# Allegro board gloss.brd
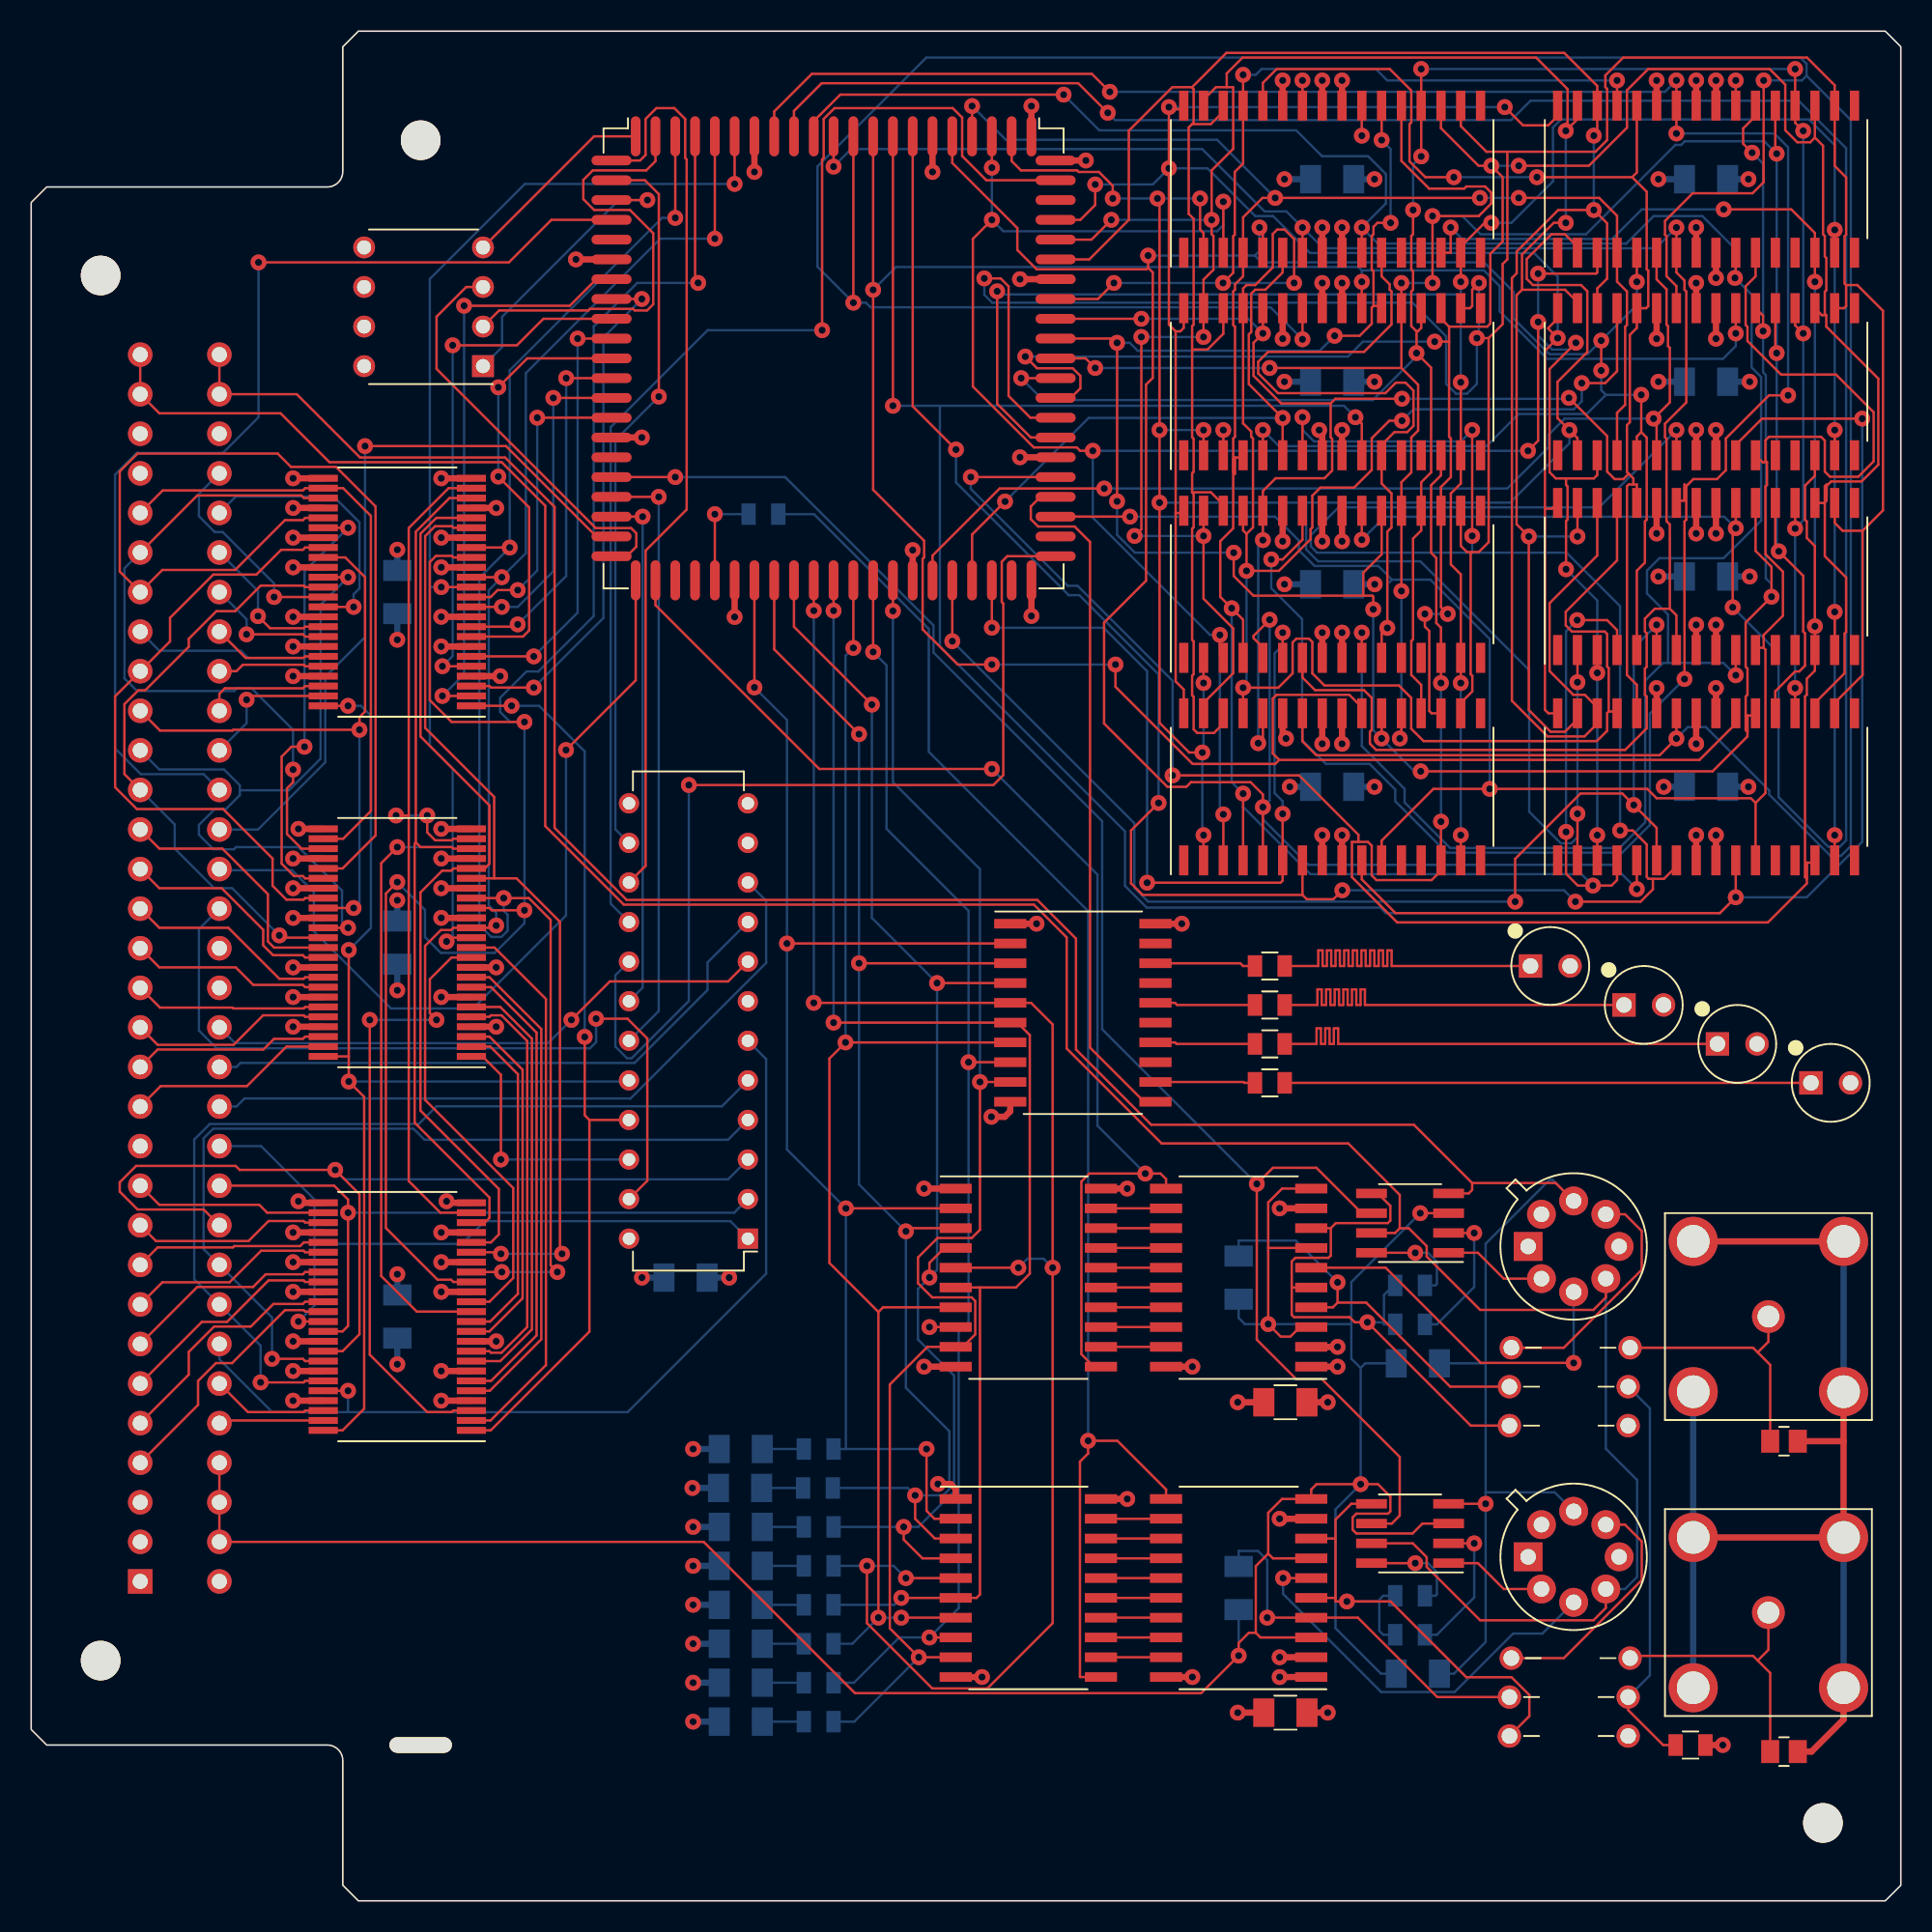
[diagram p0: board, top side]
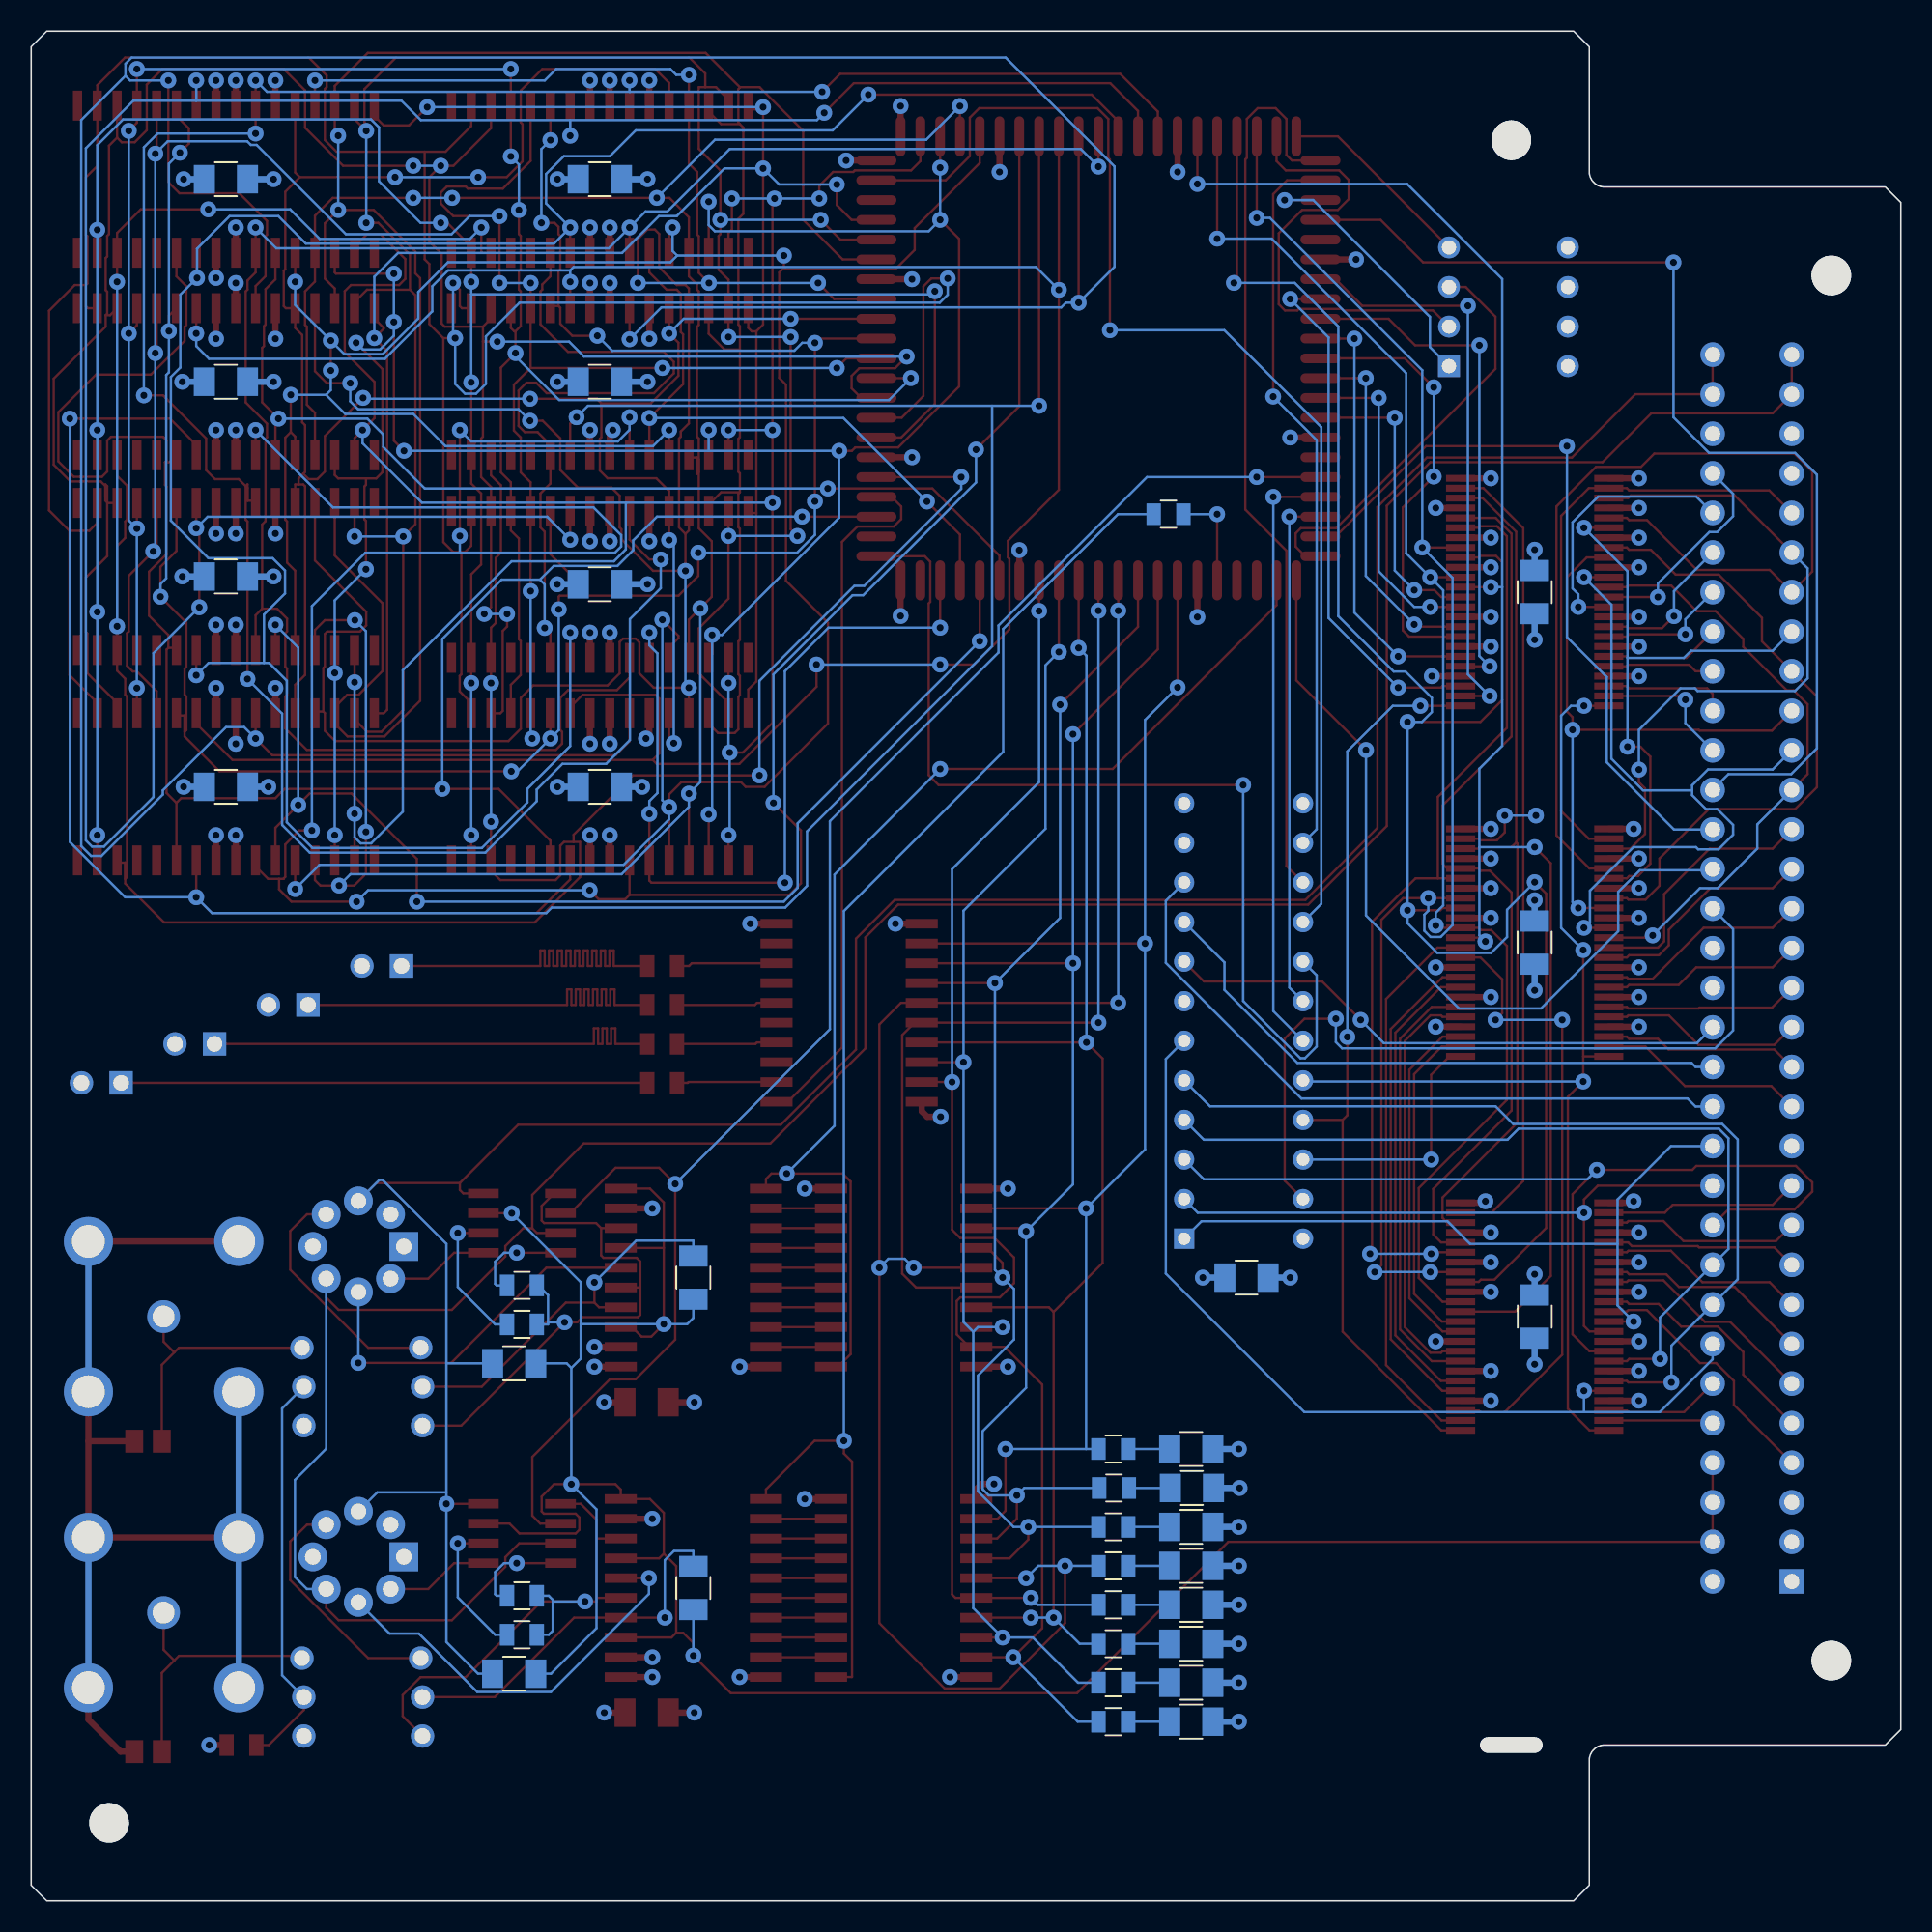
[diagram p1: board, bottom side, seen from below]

Outline 120 x 120 mm; copper layers: TOP, GND1, VCC1, VCC2, GND2, BOTTOM. Coordinates in mm from the lower left corner of the outline.

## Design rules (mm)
constraint set DEFAULT: min track width 0.15
net group LEDNETS: nets LED1 LED2 LED3 LED4
net group MEMORY[0..28]: nets MEMORY.RA0 MEMORY.RA1 MEMORY.RA2 MEMORY.RA3 MEMORY.RA4 MEMORY.RA5 MEMORY.RA6 MEMORY.RA7 MEMORY.RA8 MEMORY.RA9 MEMORY.RA10 MEMORY.RA11 MEMORY.RA12 MEMORY.RA13 MEMORY.RA14 MEMORY.RA15 MEMORY.RCS0 MEMORY.RCS1 MEMORY.RCS2 MEMORY.RCS3 MEMORY.RD0 MEMORY.RD1 MEMORY.RD2 MEMORY.RD3 MEMORY.RD4 MEMORY.RD5 MEMORY.RD6 MEMORY.RD7 MEMORY.RWE
net group POWER: nets GND_EARTH
nets with their own width: min track width 0.4; nets GND VCC

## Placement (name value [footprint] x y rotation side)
C1  0.1uF  [CAPC3216X110N]  23.5 37.5 90 bottom
C2  0.1uF  [CAPC3216X110N]  42 40 0 bottom
C3  0.1uF  [CAPC3216X110N]  23.5 61.5 90 bottom
C4  0.1uF  [CAPC3216X110N]  23.5 84 90 bottom
C5  47PF  [CAPC2012X110N]  112.5 29.5 0 top
C6  47PF  [CAPC2012X110N]  112.5 9.58 0 top
C7  0.01u  [CAPC3216X110N]  80.5 32 180 top
C8  0.01u  [CAPC3216X110N]  77.5 40 270 bottom
C9  0.1u  [CAPC3216X110N]  89 34.5 180 bottom
C10  0.01u  [CAPC3216X110N]  80.5 12.08 180 top
C11  0.01u  [CAPC3216X110N]  77.5 20.08 270 bottom
C12  0.1u  [CAPC3216X110N]  89 14.58 180 bottom
C13  330p  [CAPC3216X110N]  45.55 14 180 bottom
C14  330p  [CAPC3216X110N]  45.55 19 180 bottom
C15  330p  [CAPC3216X110N]  45.55 24 180 bottom
C16  330p  [CAPC3216X110N]  45.55 29 180 bottom
C17  330p  [CAPC3216X110N]  45.55 11.5 180 bottom
C18  330p  [CAPC3216X110N]  45.55 16.5 180 bottom
C19  330p  [CAPC3216X110N]  45.55 21.5 180 bottom
C20  330p  [CAPC3216X110N]  45.5 26.5 180 bottom
C21  0.1uF  [CAPC3216X110N]  107.5 85 0 bottom
C22  0.1uF  [CAPC3216X110N]  107.5 97.5 0 bottom
C23  0.1uF  [CAPC3216X110N]  107.5 110.5 0 bottom
C24  0.1uF  [CAPC3216X110N]  107.5 71.5 0 bottom
C25  0.1uF  [CAPC3216X110N]  83.5 71.5 0 bottom
C26  0.1uF  [CAPC3216X110N]  83.5 84.5 0 bottom
C27  0.1uF  [CAPC3216X110N]  83.5 110.5 0 bottom
C28  0.1uF  [CAPC3216X110N]  83.5 97.5 0 bottom
D1  LED  [LEDRD254W00D500H860P]  97.5 60 0 top
D2  LED  [LEDRD254W00D500H860P]  103.5 57.5 0 top
D3  LED  [LEDRD254W00D500H860P]  109.5 55 0 top
D4  LED  [LEDRD254W00D500H860P]  115.5 52.5 0 top
J1  CON64  [DIN64]  7 20.5 0 top
J2  BNC  [CONNEX_112659]  111.5 37.5 0 top
J3  BNC  [CONNEX_112659]  111.5 18.5 0 top
L1  47u  [INDAD762W79L381D254P]  95 35.5 0 top
L2  47u  [INDAD762W79L381D254P]  95 15.58 0 top
L3  47u  [INDAD762W79L381D254P]  102.5 33 180 top
L4  47u  [INDAD762W79L381D254P]  102.5 30.5 180 top
L5  47u  [INDAD762W79L381D254P]  102.5 13.08 180 top
L6  47u  [INDAD762W79L381D254P]  102.5 10.58 180 top
NOREF  -  []  26.7 0 90 top
NOREF#2  -  []  25 10 0 top
NOREF#3  -  []  119.51 119.49 0 top
NOREF#4  -  []  0 23.55 0 top
NOREF#5  -  [unnamed#2]  25 10 0 top
NOREF#6  -  []  25 10 90 top
NOREF#7  -  []  115 5 90 top
NOREF#8  -  []  20 6.63 0 top
NOREF#9  -  []  195.18 157.32 0 top
NOREF#10  -  []  25 10 90 top
NOREF#11  -  []  -74.06 -89.06 0 top
NOREF#12  -  []  19.74 110.33 0 top
NOREF#13  -  []  25 10 0 top
NOREF#14  -  []  25 10 90 top
R1  150  [RESC2012X60N]  79.5 60 0 top
R2  150  [RESC2012X60N]  79.5 57.5 0 top
R3  150  [RESC2012X60N]  79.5 55 0 top
R4  150  [RESC2012X60N]  79.5 52.5 0 top
R5  2K  [RESC2012X60N]  47 89 0 bottom
R6  100  [RESC2012X60N]  88.5 39.5 0 bottom
R7  100  [RESC2012X60N]  88.5 37 0 bottom
R8  100  [RESC2012X60N]  88.5 19.58 0 bottom
R9  100  [RESC2012X60N]  88.5 17.08 0 bottom
R10  10K  [RESC2012X60N]  50.55 14 0 bottom
R11  10K  [RESC2012X60N]  50.55 19 0 bottom
R12  10K  [RESC2012X60N]  50.55 24 0 bottom
R13  10K  [RESC2012X60N]  50.55 29 0 bottom
R14  10K  [RESC2012X60N]  50.55 11.5 0 bottom
R15  10K  [RESC2012X60N]  50.55 16.5 0 bottom
R16  10K  [RESC2012X60N]  50.55 21.5 0 bottom
R17  10K  [RESC2012X60N]  50.5 26.5 0 bottom
R18  10K  [RESC2012X60N]  106.5 10 0 top
U1  FCT16245  [SOP63P1035X279-48N]  23.5 37.5 90 top
U2  20L10  [DIP763W46P254L3204H508Q24P]  46 42.5 90 top
U3  FCT16245  [SOP63P1035X279-48N]  23.5 61.5 90 top
U4  FCT16245  [SOP63P1035X279-48N]  23.5 84 90 top
U5  EPF8282A_LCC  [PLCC127P3022X3022X457-84N]  51.5 99 270 top
U6  74ACT574  [SOIC127P1034X264-20N]  67.5 57 270 top
U7  EPC1064  [DIP763W46P254L991H419Q8P]  29 98.5 90 top
U8  TLC5602A  [SOIC127P1034X264-20N]  77.5 40 90 top
U9  TLE2037A  [TO292P469H584-8P]  99 42 0 top
U10  DG419AK  [SOIC127P600X175-8N]  88.5 43.5 90 top
U11  TLC5602A  [SOIC127P1034X264-20N]  77.5 20.08 90 top
U12  TLE2037A  [TO292P469H584-8P]  99 22.08 0 top
U13  DG419AK  [SOIC127P600X175-8N]  88.5 23.58 90 top
U14  74ACT574  [SOIC127P1034X264-20N]  64 40 270 top
U15  74ACT574  [SOIC127P1034X264-20N]  64 20.08 270 top
U16  TC55B4257  [SOIC127P1032X265-32N]  83.5 71.5 0 top
U17  TC55B4257  [SOIC127P1032X265-32N]  83.5 84.5 0 top
U18  TC55B4257  [SOIC127P1032X265-32N]  83.5 97.5 0 top
U19  TC55B4257  [SOIC127P1032X265-32N]  83.5 110.5 0 top
U20  TC55B4257  [SOIC127P1032X265-32N]  107.5 71.5 0 top
U21  TC55B4257  [SOIC127P1032X265-32N]  107.5 85 0 top
U22  TC55B4257  [SOIC127P1032X265-32N]  107.5 97.5 0 top
U23  TC55B4257  [SOIC127P1032X265-32N]  107.5 110.5 0 top

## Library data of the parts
C1-C4 C13-C20 = CAP NP
C5 C7-C9 = CAP NP: room: CHAN1
C6 C10-C12 = CAP NP: room: CHAN2
C21-C28 = CAP NP: room: MEM
D1-D4 = PHOTODIODE_0
J1 = CON64
J2 = BNC: room: CHAN1
J3 = BNC: room: CHAN2
L1 L3 L4 = INDUCTOR: room: CHAN1
L2 L5 L6 = INDUCTOR: room: CHAN2
R1-R4 = R: room: LED
R5 R10-R17 = R
R6 R7 = R: room: CHAN1
R8 R9 R18 = R: room: CHAN2
U1 U3 U4 = FCT16245
U2 = 20L10: alternate symbols: (T:SOIC24;B:SOIC24_PE)
U5 = EPF8282A/LCC
U6 = 74ACT574: room: LED
U7 = EPC1064
U8 = TLC5602A: room: CHAN1
U9 = TLE2037A: room: CHAN1
U10 = DG419AK: room: CHAN1
U11 = TLC5602A: room: CHAN2
U12 = TLE2037A: room: CHAN2
U13 = DG419AK: room: CHAN2
U14 = 74ACT574: room: CHAN1
U15 = 74ACT574: room: CHAN2
U16-U23 = TC55B4257: room: MEM

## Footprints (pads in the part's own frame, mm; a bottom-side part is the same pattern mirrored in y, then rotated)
CAPC2012X110N
  rect 1.15x1.47 smd: 1(-0.885,0) 2(0.885,0)
CAPC3216X110N
  rect 1.35x1.82 smd: 1(-1.385,0) 2(1.385,0)
CONNEX_112659
  round 2.1 hole 1.4: 1(0,0)
  round 3.15 hole 2.1: 2(-4.825,4.825) 3(4.825,4.825) 4(4.825,-4.825) 5(-4.825,-4.825)
DIN64
  round 2.54 hole 2.794 unplated: (-2.54,83.82) (-2.54,-5.08)
  rect 1.575x1.575 hole 0.965: 1(0,0)
  round 1.575 hole 0.965: 2(0,2.54) 3(0,5.08) 4(0,7.62) 5(0,10.16) 6(0,12.7) 7(0,15.24) 8(0,17.78) 9(0,20.32) 10(0,22.86) 11(0,25.4) 12(0,27.94) 13(0,30.48) 14(0,33.02) 15(0,35.56) 16(0,38.1) 17(0,40.64) 18(0,43.18) 19(0,45.72) 20(0,48.26) 21(0,50.8) 22(0,53.34) 23(0,55.88) 24(0,58.42) 25(0,60.96) 26(0,63.5) 27(0,66.04) 28(0,68.58) 29(0,71.12) 30(0,73.66) 31(0,76.2) 32(0,78.74) 33(5.08,0) 34(5.08,2.54) 35(5.08,5.08) 36(5.08,7.62) 37(5.08,10.16) 38(5.08,12.7) 39(5.08,15.24) 40(5.08,17.78) 41(5.08,20.32) 42(5.08,22.86) 43(5.08,25.4) 44(5.08,27.94) 45(5.08,30.48) 46(5.08,33.02) 47(5.08,35.56) 48(5.08,38.1) 49(5.08,40.64) 50(5.08,43.18) 51(5.08,45.72) 52(5.08,48.26) 53(5.08,50.8) 54(5.08,53.34) 55(5.08,55.88) 56(5.08,58.42) 57(5.08,60.96) 58(5.08,63.5) 59(5.08,66.04) 60(5.08,68.58) 61(5.08,71.12) 62(5.08,73.66) 63(5.08,76.2) 64(5.08,78.74)
DIP763W46P254L991H419Q8P
  rect 1.4x1.4 hole 0.9: 1(0,0)
  round 1.4 hole 0.9: 2(2.54,0) 3(5.08,0) 4(7.62,0) 5(7.62,7.63) 6(5.08,7.63) 7(2.54,7.63) 8(0,7.63)
DIP763W46P254L3204H508Q24P
  rect 1.3x1.3 hole 0.8: 1(0,0)
  round 1.3 hole 0.8: 2(2.54,0) 3(5.08,0) 4(7.62,0) 5(10.16,0) 6(12.7,0) 7(15.24,0) 8(17.78,0) 9(20.32,0) 10(22.86,0) 11(25.4,0) 12(27.94,0) 13(27.94,7.63) 14(25.4,7.63) 15(22.86,7.63) 16(20.32,7.63) 17(17.78,7.63) 18(15.24,7.63) 19(12.7,7.63) 20(10.16,7.63) 21(7.62,7.63) 22(5.08,7.63) 23(2.54,7.63) 24(0,7.63)
INDAD762W79L381D254P
  round 1.5 hole 1: 1(0,0) 2(7.62,0)
LEDRD254W00D500H860P
  round 1.5 hole 1: A(1.27,0)
  rect 1.5x1.5 hole 1: C(-1.27,0)
PLCC127P3022X3022X457-84N
  oval 2.57x0.62 smd: 1(-14.25,0) 2(-14.25,-1.27) 3(-14.25,-2.54) 4(-14.25,-3.81) 5(-14.25,-5.08) 6(-14.25,-6.35) 7(-14.25,-7.62) 8(-14.25,-8.89) 9(-14.25,-10.16) 10(-14.25,-11.43) 11(-14.25,-12.7) 33(14.25,-12.7) 34(14.25,-11.43) 35(14.25,-10.16) 36(14.25,-8.89) 37(14.25,-7.62) 38(14.25,-6.35) 39(14.25,-5.08) 40(14.25,-3.81) 41(14.25,-2.54) 42(14.25,-1.27) 43(14.25,0) 44(14.25,1.27) 45(14.25,2.54) 46(14.25,3.81) 47(14.25,5.08) 48(14.25,6.35) 49(14.25,7.62) 50(14.25,8.89) 51(14.25,10.16) 52(14.25,11.43) 53(14.25,12.7) 75(-14.25,12.7) 76(-14.25,11.43) 77(-14.25,10.16) 78(-14.25,8.89) 79(-14.25,7.62) 80(-14.25,6.35) 81(-14.25,5.08) 82(-14.25,3.81) 83(-14.25,2.54) 84(-14.25,1.27)
  oval 0.62x2.57 smd: 12(-12.7,-14.25) 13(-11.43,-14.25) 14(-10.16,-14.25) 15(-8.89,-14.25) 16(-7.62,-14.25) 17(-6.35,-14.25) 18(-5.08,-14.25) 19(-3.81,-14.25) 20(-2.54,-14.25) 21(-1.27,-14.25) 22(0,-14.25) 23(1.27,-14.25) 24(2.54,-14.25) 25(3.81,-14.25) 26(5.08,-14.25) 27(6.35,-14.25) 28(7.62,-14.25) 29(8.89,-14.25) 30(10.16,-14.25) 31(11.43,-14.25) 32(12.7,-14.25) 54(12.7,14.25) 55(11.43,14.25) 56(10.16,14.25) 57(8.89,14.25) 58(7.62,14.25) 59(6.35,14.25) 60(5.08,14.25) 61(3.81,14.25) 62(2.54,14.25) 63(1.27,14.25) 64(0,14.25) 65(-1.27,14.25) 66(-2.54,14.25) 67(-3.81,14.25) 68(-5.08,14.25) 69(-6.35,14.25) 70(-7.62,14.25) 71(-8.89,14.25) 72(-10.16,14.25) 73(-11.43,14.25) 74(-12.7,14.25)
RESC2012X60N
  rect 0.92x1.38 smd: 1(-0.955,0) 2(0.955,0)
SOIC127P600X175-8N
  rect 0.6x1.97 smd: 1(-1.905,-2.475) 2(-0.635,-2.475) 3(0.635,-2.475) 4(1.905,-2.475) 5(1.905,2.475) 6(0.635,2.475) 7(-0.635,2.475) 8(-1.905,2.475)
SOIC127P1032X265-32N
  rect 0.59x1.92 smd: 1(-9.525,-4.72) 2(-8.255,-4.72) 3(-6.985,-4.72) 4(-5.715,-4.72) 5(-4.445,-4.72) 6(-3.175,-4.72) 7(-1.905,-4.72) 8(-0.635,-4.72) 9(0.635,-4.72) 10(1.905,-4.72) 11(3.175,-4.72) 12(4.445,-4.72) 13(5.715,-4.72) 14(6.985,-4.72) 15(8.255,-4.72) 16(9.525,-4.72) 17(9.525,4.72) 18(8.255,4.72) 19(6.985,4.72) 20(5.715,4.72) 21(4.445,4.72) 22(3.175,4.72) 23(1.905,4.72) 24(0.635,4.72) 25(-0.635,4.72) 26(-1.905,4.72) 27(-3.175,4.72) 28(-4.445,4.72) 29(-5.715,4.72) 30(-6.985,4.72) 31(-8.255,4.72) 32(-9.525,4.72)
SOIC127P1034X264-20N
  rect 0.61x2.06 smd: 1(-5.715,-4.66) 2(-4.445,-4.66) 3(-3.175,-4.66) 4(-1.905,-4.66) 5(-0.635,-4.66) 6(0.635,-4.66) 7(1.905,-4.66) 8(3.175,-4.66) 9(4.445,-4.66) 10(5.715,-4.66) 11(5.715,4.66) 12(4.445,4.66) 13(3.175,4.66) 14(1.905,4.66) 15(0.635,4.66) 16(-0.635,4.66) 17(-1.905,4.66) 18(-3.175,4.66) 19(-4.445,4.66) 20(-5.715,4.66)
SOP63P1035X279-48N
  rect 0.44x1.87 smd: 1(-7.302,-4.755) 2(-6.668,-4.755) 3(-6.032,-4.755) 4(-5.398,-4.755) 5(-4.762,-4.755) 6(-4.128,-4.755) 7(-3.492,-4.755) 8(-2.858,-4.755) 9(-2.222,-4.755) 10(-1.588,-4.755) 11(-0.952,-4.755) 12(-0.318,-4.755) 13(0.318,-4.755) 14(0.952,-4.755) 15(1.588,-4.755) 16(2.222,-4.755) 17(2.858,-4.755) 18(3.492,-4.755) 19(4.128,-4.755) 20(4.762,-4.755) 21(5.398,-4.755) 22(6.032,-4.755) 23(6.668,-4.755) 24(7.302,-4.755) 25(7.302,4.755) 26(6.668,4.755) 27(6.032,4.755) 28(5.398,4.755) 29(4.762,4.755) 30(4.128,4.755) 31(3.492,4.755) 32(2.858,4.755) 33(2.222,4.755) 34(1.588,4.755) 35(0.952,4.755) 36(0.318,4.755) 37(-0.318,4.755) 38(-0.952,4.755) 39(-1.588,4.755) 40(-2.222,4.755) 41(-2.858,4.755) 42(-3.492,4.755) 43(-4.128,4.755) 44(-4.762,4.755) 45(-5.398,4.755) 46(-6.032,4.755) 47(-6.668,4.755) 48(-7.302,4.755)
TO292P469H584-8P
  rect 1.85x1.85 hole 1: 1(-2.921,0)
  round 1.85 hole 1: 2(-2.066,-2.066) 3(0,-2.921) 4(2.066,-2.066) 5(2.921,0) 6(2.066,2.066) 7(0,2.921) 8(-2.066,2.066)
unnamed#2
  round 2.54 hole 2.794 unplated: (0,103) (90,-5)
  oval 4x1 hole 5x1.5 unplated: (0,0)

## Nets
AGND: C8.2 C9.2 C11.2 C12.2 J1.34 J1.35 J1.36 U8.3 U8.7 U8.10 U10.3 U11.3 U11.7 U11.10 U13.3
GND: C1.2 C2.2 C3.2 C4.2 C7.2 C10.2 C13.2 C14.2 C15.2 C16.2 C17.2 C18.2 C19.2 C20.2 C21.2 C22.2 C23.2 C24.2 C25.2 C26.2 C27.2 C28.2 J1.1 J1.2 J1.3 J1.33 R18.2 U1.4 U1.10 U1.15 U1.21 U1.24 U1.25(G\) U1.28 U1.34 U1.39 U1.45 U2.11 U2.12 U2.13 U3.4 U3.10 U3.15 U3.21 U3.24 U3.25(G\) U3.28 U3.34 U3.39 U3.45 U4.4 U4.10 U4.15 U4.21 U4.24 U4.25(G\) U4.28 U4.34 U4.39 U4.45 U5.5 U5.26 U5.47 U5.53 U5.68 U5.74 U5.75 U6.1 U6.10 U7.5 U8.1 U8.20 U11.1 U11.20 U14.1 U14.10 U15.1 U15.10 U16.9 U16.25 U16.27 U17.9 U17.25 U17.27 U18.9 U18.25 U18.27 U19.9 U19.25 U19.27 U20.9 U20.25 U20.27 U21.9 U21.25 U21.27 U22.9 U22.25 U22.27 U23.9 U23.25 U23.27
GND_EARTH: C5.2 C6.2 J2.2 J2.3 J2.4 J2.5(GND5) J3.2 J3.3 J3.4 J3.5(GND5)
V12N: J1.31 J1.32 U9.4(V-) U10.7 U12.4(V-) U13.7
VCC: C1.1 C2.1 C3.1 C4.1 C7.1 C10.1 C21.1 C22.1 C23.1 C24.1 C25.1 C26.1 C27.1 C28.1 D1.A D2.A D3.A D4.A J1.29 J1.30 J1.62 L4.1 L6.1 U1.7 U1.18 U1.31 U1.42 U2.24(VCC) U3.7 U3.18 U3.31 U3.42 U4.7 U4.18 U4.31 U4.42 U5.17 U5.38 U5.59 U5.80 U6.20 U7.7 U7.8 U8.2 U8.9(VD2) U11.2 U11.9(VD2) U14.20 U15.20 U16.8 U16.24 U17.8 U17.24 U18.8 U18.24 U19.8 U19.24 U20.8 U20.24 U21.8 U21.24 U22.8 U22.24 U23.8 U23.24
A0: J1.54 U4.47
A1: J1.55 U4.46
A2: J1.56 U4.44
A3: J1.57 U4.43
A4: J1.58 U4.41
A5: J1.59 U4.40
A6: J1.60 U4.38
A7: J1.61 U4.37
A8: J1.13 U3.47
A9: J1.14 U3.46
A10: J1.15 U3.44
A11: J1.16 U3.43
A12: J1.17 U3.41
A13: J1.18 U3.40
A14: J1.19 U3.38
A15: J1.20 U3.37
A16: J1.37 U1.47
A17: J1.38 U1.46
A18: J1.39 U1.44 U2.6
A19: J1.40 U1.43 U2.5
A20: J1.41 U1.41 U2.4
A21: J1.42 U1.40 U2.3
A22: J1.43 U1.38 U2.2
A23: J1.44 U1.37 U2.1
AEN: J1.47 U2.8
BA0: U1.13 U3.13 U4.13 U5.6
BA1: U1.14 U3.14 U4.14 U5.7
BA2: U1.16 U3.16 U4.16 U5.8
BA3: U1.17 U3.17 U4.17 U5.9
BA4: U1.19 U3.19 U4.19
BA5: U1.20 U3.20 U4.20
BA6: U1.22 U3.22 U4.22
BA7: U1.23 U3.23 U4.23
BD0: U4.12 U5.25
BD1: U4.11 U5.24
BD2: U4.9 U5.23
BD3: U4.8 U5.22
BD4: U4.6 U5.21
BD5: U4.5 U5.20
BD6: U4.3 U5.19
BD7: U4.2 U5.18
BD8: U1.12 U3.2
BD9: U1.11 U3.3
BD10: U1.9 U3.5
BD11: U1.8 U3.6
BD12: U1.6 U3.8
BD13: U1.5 U3.9
BD14: U1.3 U3.11
BD15: U1.2 U3.12
BNC2: C5.1 J2.1 L1.2
BNC3: C6.1 J3.1 L2.2
BRD: U2.16 U5.73
BRESET: U2.15 U5.12
BWR: U2.17 U5.54
D0: J1.28 U3.26 U4.26
D1: J1.27 U3.27 U4.27
D2: J1.26 U3.29 U4.29
D3: J1.25 U3.30 U4.30
D4: J1.24 U3.32 U4.32
D5: J1.23 U3.33 U4.33
D6: J1.22 U3.35 U4.35
D7: J1.21 U3.36 U4.36
D8: J1.4 U1.36
D9: J1.5 U1.35
D10: J1.6 U1.33
D11: J1.7 U1.32
D12: J1.8 U1.30
D13: J1.9 U1.29
D14: J1.10 U1.27
D15: J1.11 U1.26
DATA: U5.14 U7.1
DCLK: U5.10 U7.2
DDIR: U1.48 U2.20 U3.48 U4.48
DEN: U1.1 U2.21 U4.1
DHEN: U2.22 U3.1
FPGA: U2.18 U5.30
GAIN: U5.28 U10.6 U13.6
HS: U2.19 U5.29
LED1: D1.C(CATHODE) R1.2
LED2: D2.C(CATHODE) R2.2
LED3: D3.C(CATHODE) R3.2
LED4: D4.C(CATHODE) R4.2
MCLK: J1.52 U5.31
MEMORY.RA0: U5.79 U16.5 U17.5 U18.5 U19.5 U20.5 U21.5 U22.5 U23.5
MEMORY.RA1: U5.78 U16.4 U17.4 U18.4 U19.4 U20.4 U21.4 U22.4 U23.4
MEMORY.RA2: U5.77 U16.3 U17.3 U18.3 U19.3 U20.3 U21.3 U22.3 U23.3
MEMORY.RA3: U5.76 U16.2 U17.2 U18.2 U19.2 U20.2 U21.2 U22.2 U23.2
MEMORY.RA4: U5.71 U16.32 U17.32 U18.32 U19.32 U20.32 U21.32 U22.32 U23.32
MEMORY.RA5: U5.70 U16.31 U17.31 U18.31 U19.31 U20.31 U21.31 U22.31 U23.31
MEMORY.RA6: U5.69 U16.30 U17.30 U18.30 U19.30 U20.30 U21.30 U22.30 U23.30
MEMORY.RA7: U5.67 U16.29 U17.29 U18.29 U19.29 U20.29 U21.29 U22.29 U23.29
MEMORY.RA8: U5.66 U16.28 U17.28 U18.28 U19.28 U20.28 U21.28 U22.28 U23.28
MEMORY.RA9: U5.65 U16.22 U17.22 U18.22 U19.22 U20.22 U21.22 U22.22 U23.22
MEMORY.RA10: U5.64 U16.21 U17.21 U18.21 U19.21 U20.21 U21.21 U22.21 U23.21
MEMORY.RA11: U5.63 U16.20 U17.20 U18.20 U19.20 U20.20 U21.20 U22.20 U23.20
MEMORY.RA12: U5.62 U16.19 U17.19 U18.19 U19.19 U20.19 U21.19 U22.19 U23.19
MEMORY.RA13: U5.61 U16.18 U17.18 U18.18 U19.18 U20.18 U21.18 U22.18 U23.18
MEMORY.RA14: U5.60 U16.15 U17.15 U18.15 U19.15 U20.15 U21.15 U22.15 U23.15
MEMORY.RA15: U5.58 U16.14 U17.14 U18.14 U19.14 U20.14 U21.14 U22.14 U23.14
MEMORY.RCS0: U5.51 U16.6 U17.6
MEMORY.RCS1: U5.50 U18.6 U19.6
MEMORY.RCS2: U5.49 U20.6 U21.6
MEMORY.RCS3: U5.48 U22.6 U23.6
MEMORY.RD0: U5.81 U16.7 U18.7 U20.7 U22.7
MEMORY.RD1: U5.82 U16.10 U18.10 U20.10 U22.10
MEMORY.RD2: U5.83 U16.23 U18.23 U20.23 U22.23
MEMORY.RD3: U5.84 U16.26 U18.26 U20.26 U22.26
MEMORY.RD4: U5.1 U17.7 U19.7 U21.7 U23.7
MEMORY.RD5: U5.2 U17.10 U19.10 U21.10 U23.10
MEMORY.RD6: U5.3 U17.23 U19.23 U21.23 U23.23
MEMORY.RD7: U5.4 U17.26 U19.26 U21.26 U23.26
MEMORY.RWE: U5.56 U16.11(W\E\) U17.11(W\E\) U18.11(W\E\) U19.11(W\E\) U20.11(W\E\) U21.11(W\E\) U22.11(W\E\) U23.11(W\E\)
MRD: J1.46 U2.9
MWR: J1.45 U2.10
N00036_DATA_DAAMP: L4.2 R6.1 R7.1 U8.5 U8.8 U10.5(VL)
N00036_DATA_DAAMP1: L6.2 R8.1 R9.1 U11.5 U11.8 U13.5(VL)
N00038_DATA_DAAMP: C8.1 L3.2 U8.4
N00038_DATA_DAAMP1: C11.1 L5.2 U11.4
N00044_DATA_DAAMP: U9.2 U10.1
N00044_DATA_DAAMP1: U12.2 U13.1
N00060_DATA_DAAMP: U8.6 U9.3
N00060_DATA_DAAMP1: U11.6 U12.3
N282866_DATA_DAAMP: R6.2 U10.8
N282866_DATA_DAAMP1: R8.2 U13.8
N282912_DATA_DAAMP: R7.2 U10.2
N282912_DATA_DAAMP1: R9.2 U13.2
NCS: U5.11 U7.4
OE: U5.32 U7.3(OE)
OUTA: L1.1 U9.6
OUTB: L2.1 U12.6
Q0: R1.1 U6.18
Q1: R2.1 U6.16
Q2: R3.1 U6.14
Q3: R4.1 U6.12(Q8)
RDY: J1.50 U2.23
RESET: J1.53 U5.15
SEL: U2.14 U5.13
V+12: C9.1 C12.1 J1.63 J1.64 U9.7 U10.4 U12.7 U13.4
VCLKA: U5.34 U8.11 U14.11
VCLKC: R5.2 U11.11 U15.11
VD0: R13.2 U5.39 U6.2 U14.2 U15.2
VD1: R17.2 U5.40 U6.3 U14.3 U15.3
VD2: R12.2 U5.41 U6.4 U14.4 U15.4
VD3: R16.2 U5.42 U6.5 U14.5 U15.5
VD4: R11.2 U5.43 U6.6 U14.6 U15.6
VD5: R15.2 U5.44 U6.7 U14.7 U15.7
VD6: R10.2 U5.45 U6.8 U14.8 U15.8
VD7: R14.2 U5.46(VD7) U6.9 U14.9 U15.9
VREF: L3.1 L5.1 R18.1
WAIT: J1.51 U5.33
WSTAT: U5.57 U6.11
N14843: C19.1 R16.1
N14849: C15.1 R12.1
N14853: C20.1 R17.1
N14855: C16.1 R13.1
N15143: C17.1 R14.1
N15151: C13.1 R10.1
N15155: C18.1 R15.1
N15161: C14.1 R11.1
N58063: U8.12 U14.19
N58118: U8.13 U14.18
N58173: U8.14 U14.17
N58228: U8.15 U14.16
N58283: U8.16 U14.15
N58338: U8.17 U14.14
N58393: U8.18 U14.13
N58448: U8.19 U14.12(Q8)
N58834: U11.12 U15.19
N58889: U11.13 U15.18
N58944: U11.14 U15.17
N58999: U11.15 U15.16
N59054: U11.16 U15.15
N59109: U11.17 U15.14
N59164: U11.18 U15.13
N59219: U11.19 U15.12(Q8)
N409523: R5.1 U5.37

Pads without a net: J1 12 48 49; U2 7; U5 16 27 35 36 52 55 72; U6 13 15 17 19; U7 6; U9 1 5 8; U12 1 5 8; U16 1 12 13 16 17; U17 1 12 13 16 17; U18 1 12 13 16 17; U19 1 12 13 16 17; U20 1 12 13 16 17; U21 1 12 13 16 17; U22 1 12 13 16 17; U23 1 12 13 16 17

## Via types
v1: diameter 1.016, hole 0.457, TOP to BOTTOM, 470 vias

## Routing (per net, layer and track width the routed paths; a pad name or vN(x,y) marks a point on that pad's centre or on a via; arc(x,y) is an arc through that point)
AGND: length 179.8
  TOP w0.15: U11.7 79.7,21.98 79.4,22.28 ; 79.4,22.28 79.4,24.91 80.29,25.79 U11.10 82.16,26.4 82.5,26.74 v1(85.33,26.74) 86.44,26.74 87.23,25.95 87.23,24.99 87.09,24.85 85.05,24.85 84.81,24.61 84.81,23.82 85.05,23.58 88.66,23.58 89.3,24.21 U13.3 ; 79.4,22.28 78.6,21.49 78.6,17.2 ; U8.3 81.44,36.83 80.82,36.21 80.2,36.21 v1(79.4,37.02) 79.4,41.91 ; U10.3 v1(89.15,44.13) ; 78.6,17.2 78.15,17.2 77.5,16.55 v1(77.5,15.74) 75.09,13.33 52.87,13.33 43.16,23.04 J1.34 J1.35 J1.36 ; 78.6,17.2 78.9,16.9 U11.3 ; 79.4,41.91 79.4,44.83 80.29,45.72 U8.10 ; 79.4,41.91 U8.7
  BOTTOM w0.15: 84.73,37.02 v1(79.4,37.02) 77.9,37.02 77.5,37.41 C8.2 ; 84.73,37.02 84.73,39.71 v1(89.15,44.13) ; 84.73,37.02 84.73,34.8 85.33,34.2 ; 85.33,34.2 85.63,34.5 C9.2 ; 85.33,34.2 v1(85.33,26.74) 83.72,25.13 83.72,17.5 86.64,14.58 C12.2 ; C11.2 v1(77.5,15.74)
GND: length 164.5
  TOP w0.4: U17.25 v1(82.87,87.26) ; C10.2 v1(77.44,12.08) ; U21.9 v1(108.14,81.9) ; U3.4 v1(29.85,56.1) ; 18.75,91.3 v1(16.81,91.3) ; U4.15 v1(26.32,85.59) ; v1(26.66,44.9) 26.76,44.8 U1.24 ; U18.25 v1(82.87,103.84) ; U14.1 v1(57.31,45.72) ; U3.15 v1(26.32,63.09) ; U6.10 62.84,50.67 62.49,50.32 v1(61.63,50.32) ; U16.9 v1(84.13,68.4) ; U1.15 v1(26.32,39.09) ; U5.75 v1(64.2,115.19) ; U4.4 v1(30.1,78.6) ; U5.5 v1(46.42,110.97) ; U4.45 v1(16.81,78.6) ; U1.39 v1(16.81,35.91) ; U5.74 v1(67.69,111.7) ; R18.2 v1(108.57,10) ; U16.27 80.33,74.81 v1(80.54,74.6) ; U19.9 v1(84.13,107.4) ; U3.21 v1(26.32,66.9) ; U4.28 v1(16.81,89.4) ; U4.24 v1(26.32,91.3) ; U1.28 v1(16.81,42.9) ; U21.25 v1(106.86,87.76) ; U5.47 v1(56.58,86.69) ; U1.4 v1(26.32,32.1) ; U1.10 v1(29.85,35.91) ; U5.53 v1(64.2,82.47) ; U6.1 v1(64.53,62.72) ; v1(58.2,26.76) 59.01,26.76 59.34,26.43 U15.1 ; U17.27 v1(80.33,87.26) ; U19.25 v1(82.87,116.84) ; 18.75,44.8 17.25,44.8 v1(17.15,44.9) ; U14.10 v1(57.31,34.28) ; U23.27 v1(104.33,116.84) ; U15.10 v1(61.03,14.36) ; U8.1 v1(83.85,34.28) ; U18.9 v1(84.14,94.4) ; 18.75,68.8 v1(17.15,68.8) ; U1.45 v1(16.81,32.1) ; U3.39 v1(16.81,59.91) ; U4.10 v1(26.32,82.41) ; U3.28 v1(16.81,66.9) ; U11.1 v1(80.13,14.36) ; U20.9 v1(108.14,68.4) ; U16.25 v1(82.87,74.26) ; U3.10 v1(29.85,59.91) ; U3.34 v1(16.81,63.09) ; U3.45 v1(16.81,56.1) ; U8.20 v1(74.53,34.28) ; U22.27 v1(104.33,100.26) ; U23.25 v1(106.86,116.84) ; U20.25 v1(106.86,74.26) ; C7.2 v1(77.44,32) ; U21.27 v1(104.33,87.76) ; U4.39 v1(16.81,82.41) ; U4.21 v1(29.85,89.4) ; U22.25 v1(106.86,103.84) ; U22.9 v1(108.14,94.4) ; U3.24 v1(26.32,68.8) ; U5.68 v1(63.47,104.08) ; U17.9 v1(84.13,81.4) ; U11.20 v1(74.53,14.36) ; U18.27 v1(80.33,100.26) ; U23.9 v1(108.14,104.16) ; U20.27 v1(104.33,77.84) ; U4.34 v1(16.81,85.59) ; U5.26 v1(39.19,93.92) ; U1.34 v1(16.81,39.09) ; U1.21 v1(26.32,42.9) ; U19.27 v1(80.33,116.84)
  BOTTOM w0.4: C17.2 v1(42.48,11.5) ; C23.2 v1(110.22,110.5) ; C1.2 v1(23.5,40.22) ; C3.2 v1(23.5,64.22) ; C13.2 v1(42.48,14) ; C2.2 v1(44.8,40) ; C14.2 v1(42.48,19) ; C24.2 108.89,71.5 v1(110.22,71.5) ; C28.2 v1(86.22,97.5) ; C25.2 v1(86.22,71.5) ; C16.2 v1(42.48,29) ; C4.2 v1(23.5,86.72) ; C22.2 v1(110.3,97.5) ; C15.2 v1(42.48,24) ; C18.2 v1(42.48,16.5) ; C19.2 v1(42.48,21.5) ; C26.2 v1(86.23,84.5) ; C21.2 v1(110.3,85) ; C27.2 v1(86.22,110.5) ; C20.2 v1(42.44,26.5)
GND_EARTH: length 75.7
  TOP w0.4: 116.33,29.5 J2.4 ; 116.33,29.5 C5.2 ; 116.33,29.5 J3.3 J3.2 ; C6.2 114.27,9.58 116.33,11.64 J3.4 ; J2.2 J2.3
  BOTTOM w0.4: J2.5 J3.2 J3.5 ; J3.3 J3.4 ; J2.3 J2.4
V12N: length 183.6
  TOP w0.15: 87.84,43.16 87.54,42.87 U10.7 ; 87.84,43.16 88.42,43.16 89.57,42.02 89.57,41.36 93,37.93 100.27,37.93 101.07,38.72 U9.4 ; 87.84,43.16 87.84,45.31 84.54,48.61 72.56,48.61 66.46,54.71 66.46,61.84 64.36,63.94 38.03,63.94 32.99,68.98 32.99,89.54 30.2,92.33 19.15,92.33 16.01,95.47 8.23,95.47 J1.31 J1.32 ; U13.7 88.68,22.94 89.57,22.05 89.57,21.44 93,18.01 100.27,18.01 101.07,18.8 101.07,20.01
  BOTTOM w0.15: 101.07,20.01 102.3,20.01 103.07,20.79 103.07,27.01 101.07,29.02 U9.4
VCC: length 94.4
  TOP w0.4: U15.20 v1(70.35,25.79) ; U20.24 v1(108.14,77.84) ; U11.2 v1(80.13,15.63) ; U3.7 v1(26.32,58.01) ; U3.31 v1(16.81,64.99) ; U14.20 v1(70.35,45.72) ; U4.42 v1(16.81,80.51) ; U22.8 v1(106.86,94.4) ; U5.17 v1(34.97,105.35) ; U23.24 v1(108.14,116.84) ; U11.9 v1(80.13,24.52) ; U23.8 v1(106.86,107.4) ; U4.18 v1(26.32,87.49) ; U8.9 v1(80.13,44.45) ; U4.31 v1(16.81,87.49) ; U16.8 v1(82.87,68.4) ; U5.38 v1(45.15,82.4) ; U3.42 v1(16.81,58.01) ; U1.7 v1(26.32,34.01) ; U19.8 v1(82.87,107.4) ; U21.8 v1(106.86,81.9) ; U1.18 v1(26.32,40.99) ; U1.42 v1(16.81,34.01) ; U17.24 v1(84.13,87.26) ; v1(82.67,94.4) 82.87,94.2 U18.8 ; U17.8 v1(82.87,81.4) ; U18.24 v1(84.13,103.84) ; U16.24 v1(84.13,74.26) ; U3.18 v1(26.32,64.99) ; U1.31 v1(16.81,40.99) ; U8.2 v1(83.85,35.55) ; U4.7 v1(26.32,80.51) ; C10.1 v1(83.22,12.08) ; U5.59 v1(63.47,92.65) ; U6.20 v1(73.85,62.72) ; C7.1 v1(83.22,32) ; U20.8 v1(106.86,68.4) ; U22.24 v1(108.14,100.26) ; U5.80 v1(57.85,110.97) ; U19.24 v1(84.13,116.84) ; U21.24 v1(108.14,87.76)
  BOTTOM w0.4: C26.1 v1(80.44,84.5) ; C23.1 v1(104.44,110.5) ; C27.1 v1(80.44,110.5) ; C24.1 106.11,71.5 v1(104.78,71.5) ; C4.1 v1(23.5,80.94) ; C3.1 v1(23.5,58.44) ; C28.1 v1(80.44,97.5) ; C25.1 v1(80.78,71.5) ; C2.1 v1(39.2,40) ; C22.1 v1(104.44,97.5) ; C21.1 v1(104.44,85) ; C1.1 v1(23.5,34.44)
A0: length 9
  TOP w0.15: U4.47 14.07,77.33 v1(13.83,77.09)
  BOTTOM w0.15: v1(13.83,77.09) 13.83,75.59 J1.54
A1: length 8
  TOP w0.15: J1.55 12.08,77.47 12.43,77.82 17.44,77.82 17.59,77.97 U4.46
A2: length 6.9
  TOP w0.15: J1.56 13.17,78.92 13.59,79.33 17.49,79.33 17.59,79.24 U4.44
A3: length 7.4
  TOP w0.15: U4.43 17.59,79.87 17.49,79.78 13.77,79.78 J1.57
A4: length 8.4
  TOP w0.15: v1(13.83,81.29) 17.44,81.29 17.59,81.14 U4.41
  BOTTOM w0.15: v1(13.83,81.29) 13.83,82.25 J1.58
A5: length 9.7
  TOP w0.15: U4.40 17.59,81.78 17.49,81.68 15.33,81.68 v1(14.56,82.45)
  BOTTOM w0.15: v1(14.56,82.45) 14.56,84.06 J1.59
A6: length 17.6
  TOP w0.15: U4.38 v1(20.7,83.05)
  BOTTOM w0.15: J1.60 13.13,90.13 19.42,90.13 21.07,88.48 21.07,84.23 20.7,83.86 v1(20.7,83.05)
A7: length 13.9
  TOP w0.15: U4.37 v1(15.59,83.68)
  BOTTOM w0.15: v1(15.59,83.68) 15.59,84.55 12.29,87.85 11.78,87.85 10.77,88.87 10.77,90.31 J1.61
A8: length 13.3
  TOP w0.15: U3.47 16.39,54.83 13.85,52.29 8.31,52.29 J1.13
A9: length 12.6
  TOP w0.15: J1.14 8.12,54.64 14.9,54.64 15.59,55.32 17.44,55.32 17.59,55.47 U3.46
A10: length 13
  TOP w0.15: J1.15 8.12,54.94 12.99,54.94 14.89,56.84 17.49,56.84 17.59,56.74 U3.44
A11: length 12.3
  TOP w0.15: U3.43 17.59,57.37 17.49,57.27 12.98,57.27 12.92,57.33 8.27,57.33 J1.16
A12: length 12.8
  TOP w0.15: U3.41 17.59,58.64 17.44,58.79 14.26,58.79 13.13,59.91 8.23,59.91 J1.17
A13: length 13.7
  TOP w0.15: U3.40 17.59,59.28 17.49,59.18 15.93,59.18 12.66,62.45 8.23,62.45 J1.18
A14: length 14.7
  TOP w0.15: J1.19 8.23,64.99 12.23,64.99 14.89,62.33 14.89,61.33 15.53,60.69 17.44,60.69 17.59,60.55 U3.38
A15: length 16.7
  TOP w0.15: J1.20 8.23,67.53 12.27,67.53 15.19,64.61 15.19,61.58 15.59,61.18 U3.37
A16: length 6.7
  TOP w0.15: U1.47 12.25,30.83 J1.37
A17: length 7.5
  TOP w0.15: J1.38 13.91,31.37 17.49,31.37 17.59,31.47 U1.46
A18: length 59.6
  TOP w0.15: U1.44 v1(20.34,32.74)
  BOTTOM w0.15: v1(20.34,32.74) 20.34,31.37 ; 20.34,31.37 15.47,31.37 12.08,34.76 J1.39 ; 20.34,31.37 38.28,31.37 47.17,40.26 47.17,54.02 U2.6
A19: length 58.5
  TOP w0.15: U1.43 17.59,33.37 17.49,33.27 v1(14.73,33.27)
  BOTTOM w0.15: U2.5 44.34,50.99 26.01,50.99 24.88,49.86 11.46,49.86 10.47,48.86 10.47,39.89 J1.40 14.73,35.63 v1(14.73,33.27)
A20: length 55.3
  TOP w0.15: U1.41 17.59,34.64 17.44,34.79 v1(15.46,34.79)
  BOTTOM w0.15: v1(15.46,34.79) 15.46,37.44 J1.41 11.07,41.83 11.07,48.95 11.68,49.56 24.54,49.56 25.25,48.85 44.73,48.85 U2.4
A21: length 63.5
  TOP w0.15: U1.40 19.98,35.28 21.07,36.36 21.07,45.36 v1(19.51,46.91) 13.38,46.91 13.12,47.17 6.74,47.17 5.69,46.12 5.69,45.52 6.83,44.37 11.07,44.37 J1.42
  BOTTOM w0.15: U2.3 44.73,46.31 20.12,46.31 v1(19.51,46.91)
A22: length 44.5
  TOP w0.15: U1.38 19.98,36.55 20.34,36.9 v1(20.34,44.16) 20.34,45.01 19.45,45.9 J1.43
  BOTTOM w0.15: U2.2 45.12,44.16 v1(20.34,44.16)
A23: length 46.3
  TOP w0.15: U1.37 v1(17.15,37.18)
  BOTTOM w0.15: 18.18,42.16 18.18,38.22 v1(17.15,37.18) ; 18.18,42.16 18.18,45.01 14.76,48.44 J1.44 ; 18.18,42.16 27.65,42.16 29.1,43.62 44.88,43.62 U2.1
AEN: length 36.5
  TOP w0.15: U2.8 44.73,59.01 37.14,59.01 v1(34.67,56.54)
  BOTTOM w0.15: J1.47 13.09,55.05 33.18,55.05 v1(34.67,56.54)
BA0: length 111
  TOP w0.15: v1(23.5,67.63) 22.47,66.6 22.47,40.1 24.75,37.82 U1.13 ; U3.13 26.91,61.82 v1(26.66,61.57) ; v1(26.32,84.32) U4.13 ; v1(45.15,110.19) U5.6
  BOTTOM w0.15: 25.59,84.32 25.59,104.1 31.68,110.19 v1(45.15,110.19) ; 25.59,84.32 25.59,74.13 27.05,72.66 27.05,67.63 ; 25.59,84.32 v1(26.32,84.32) ; 27.05,67.63 27.05,61.97 v1(26.66,61.57) ; 27.05,67.63 v1(23.5,67.63)
BA1: length 92.9
  TOP w0.15: U1.14 29.42,38.45 30.94,39.98 30.94,45.75 25.28,51.41 25.28,61.29 26.3,62.31 26.95,62.31 27.09,62.45 U3.14 29.7,62.45 v1(29.85,62.6) ; U5.7 v1(43.88,106.68) ; U4.14 v1(30.21,84.95)
  BOTTOM w0.15: v1(29.85,62.6) 29.85,63.41 29.37,63.89 29.37,84.12 v1(30.21,84.95) 31.75,86.49 31.75,98.05 40.38,106.68 v1(43.88,106.68)
BA2: length 122.9
  TOP w0.15: v1(23.5,65.38) 22.77,64.65 22.77,43.18 26.08,39.87 26.95,39.87 27.09,39.72 U1.16 ; v1(31.66,63.58) 29.56,63.58 29.41,63.72 U3.16 ; U4.16 27.09,86.22 27,86.32 25.98,86.32 25.59,85.92 25.59,77.06 26.98,75.67 v1(31.66,75.67) ; v1(42.81,103.84) 42.61,104.04 U5.8
  BOTTOM w0.15: v1(23.5,65.38) 25.27,63.61 25.27,61.86 26.29,60.84 29.76,60.84 31.66,62.75 v1(31.66,63.58) v1(31.66,75.67) 30.74,75.67 30.1,76.3 30.1,77.21 31.79,78.9 32.55,78.9 36.11,82.46 36.11,101.05 38.9,103.84 v1(42.81,103.84)
BA3: length 97.2
  TOP w0.15: U4.17 v1(30.71,86.86) ; v1(33.77,40.36) 33.34,40.79 33.34,62.96 31.94,64.36 v1(30.33,64.36) U3.17 ; U1.17 v1(30.21,40.36) ; U5.9 v1(41.34,108.02)
  BOTTOM w0.15: v1(41.34,108.02) 40.49,108.02 30.71,98.24 v1(30.71,86.86) 28.77,84.91 28.77,62.63 29.53,61.87 30.18,61.87 30.58,62.26 30.58,63.29 30.33,63.55 v1(30.33,64.36) ; v1(30.21,40.36) v1(33.77,40.36)
BA4: length 61.1
  TOP w0.15: U3.19 29.71,65.63 ; 29.71,65.63 29.71,70.85 25.29,75.28 25.29,87.59 25.92,88.22 27,88.22 27.09,88.13 U4.19 ; 29.71,65.63 31.15,65.63 33.94,62.83 33.94,41.66 v1(34.07,41.53) ; v1(30.15,41.53) 30.05,41.63 U1.19
  BOTTOM w0.15: v1(34.07,41.53) v1(30.15,41.53)
BA5: length 57.9
  TOP w0.15: U4.20 26,88.76 24.99,87.75 24.99,74.73 29.41,70.31 29.41,66.56 29.12,66.26 U3.20 27.09,66.26 26.95,66.12 26.38,66.12 24.98,64.72 24.98,50.73 30.02,45.69 30.02,42.77 29.51,42.26 U1.20
BA6: length 55.5
  TOP w0.15: U3.22 27.09,67.53 27,67.63 24.99,67.63 24.69,67.93 ; U1.22 29.12,43.53 29.41,43.83 29.41,45.14 24.61,49.94 24.61,67.85 24.69,67.93 ; 24.69,67.93 24.69,87.87 26.85,90.03 U4.22
BA7: length 58.8
  TOP w0.15: U1.23 26.27,44.17 24.23,46.2 24.23,69.66 ; U4.23 26.79,90.67 24.23,88.11 24.23,69.66 ; 24.23,69.66 v1(23.42,69.66) ; v1(25.42,69.66) 25.42,68.58 25.93,68.07 27,68.07 27.09,68.17 U3.23
  BOTTOM w0.15: v1(23.42,69.66) v1(25.42,69.66)
BD0: length 19.5
  TOP w0.15: U5.25 v1(32.48,95.19) ; U4.12 29.5,83.68 29.94,84.13 v1(31.23,84.13)
  BOTTOM w0.15: v1(31.23,84.13) 32.48,85.38 v1(32.48,95.19)
BD1: length 21.1
  TOP w0.15: U5.24 v1(33.51,96.46) ; U4.11 v1(30.21,83.05)
  BOTTOM w0.15: v1(30.21,83.05) 31.23,83.05 33.51,85.33 v1(33.51,96.46)
BD2: length 23
  TOP w0.15: v1(31.23,81.92) 31.08,81.78 U4.9 ; U5.23 v1(34.34,97.73)
  BOTTOM w0.15: v1(34.34,97.73) 34.34,85.03 v1(31.23,81.92)
BD3: length 28.3
  TOP w0.15: U5.22 31.84,99 v1(29.98,97.14) ; v1(29.98,91.41) 31.96,89.43 31.96,81.54 31.57,81.14 U4.8
  BOTTOM w0.15: v1(29.98,91.41) v1(29.98,97.14)
BD4: length 27.7
  TOP w0.15: U4.6 v1(32.26,79.87) ; U5.21 v1(35.07,100.27)
  BOTTOM w0.15: v1(35.07,100.27) 35.07,82.68 v1(32.26,79.87)
BD5: length 33.6
  TOP w0.15: U5.20 32.88,101.54 31.17,99.84 v1(27.05,99.84) ; U4.5 v1(26.39,79.24)
  BOTTOM w0.15: v1(26.39,79.24) 27.05,79.9 v1(27.05,99.84)
BD6: length 33.8
  TOP w0.15: 28.25,77.97 29.41,77.97 29.51,77.87 v1(32.26,77.87) ; U5.19 v1(39.19,102.81)
  BOTTOM w0.15: v1(39.19,102.81) 36.73,100.34 36.73,82.34 v1(32.26,77.87)
BD7: length 37.6
  TOP w0.15: U5.18 36.27,104.08 34.57,102.38 v1(27.79,102.38) ; 28.25,77.33 v1(26.39,77.33)
  BOTTOM w0.15: v1(27.79,102.38) 27.79,78.72 v1(26.39,77.33)
BD8: length 21.5
  TOP w0.15: 28.25,54.83 29.46,54.83 31.24,53.05 31.24,38.96 29.46,37.18 U1.12
BD9: length 23
  TOP w0.15: U1.11 29.41,36.55 31.54,38.67 31.54,53.34 29.41,55.47 28.25,55.47
BD10: length 27
  TOP w0.15: U1.9 29.41,35.28 29.51,35.18 30.19,35.18 31.84,36.83 31.84,55.18 30.19,56.84 29.51,56.84 29.41,56.74 U3.5
BD11: length 28.1
  TOP w0.15: U3.6 30.11,57.37 32.14,55.34 32.14,36.67 30.11,34.64 U1.8
BD12: length 30.2
  TOP w0.15: U3.8 29.52,58.64 32.44,55.72 32.44,36.29 29.52,33.37 U1.6
BD13: length 31.6
  TOP w0.15: U3.9 29.41,59.28 32.74,55.95 32.74,36.04 29.44,32.74 U1.5
BD14: length 39.9
  TOP w0.15: v1(26.02,56.54) 25.59,56.97 25.59,59.15 26.98,60.55 U3.11 ; v1(21.73,56.54) 21.73,35.05 25.42,31.37 27,31.37 27.09,31.47 28.25,31.47
  BOTTOM w0.15: v1(21.73,56.54) v1(26.02,56.54)
BD15: length 35.9
  TOP w0.15: 28.25,30.83 29.48,30.83 33.04,34.39 33.04,57.88 29.74,61.18 U3.12
BNC2: length 16.9
  TOP w0.15: 110.81,35.2 111.5,35.89 J2.1 ; 110.81,35.2 110.52,35.5 L1.2 ; 110.81,35.2 111.61,34.4 C5.1
BNC3: length 17.9
  TOP w0.15: 110.81,15.43 110.52,15.72 102.77,15.72 L2.2 ; 110.81,15.43 111.61,14.62 C6.1 ; 110.81,15.43 111.5,16.11 J3.1
BRD: length 80.5
  TOP w0.15: U5.73 61.31,110.43 59.76,111.98 59.76,114.45 59.15,115.06 51.56,115.06 50.86,114.37 50.86,111.86 50.77,111.77 v1(50.77,100.81)
  BOTTOM w0.15: U2.16 37.2,63.99 37.2,94.58 43.42,100.81 v1(50.77,100.81)
BRESET: length 58.3
  TOP w0.15: U2.15 39.44,66.42 39.44,86.66 42.07,89.3 42.07,111.77 41.98,111.87 41.98,114.36 41.28,115.06 40.13,115.06 39.44,114.37 39.44,112.05 39.08,111.7 U5.12
BWR: length 64
  TOP w0.15: v1(42.21,71.62) 61.76,71.62 62.39,72.25 62.39,83.27 62.3,83.37 62.3,85.95 62.65,86.3 U5.54
  BOTTOM w0.15: v1(42.21,71.62) 42.21,57.75 38.54,54.08 38.25,54.08 37.49,54.83 37.49,59.41 U2.17
D0: length 38.9
  TOP w0.15: 18.75,68.17 20.03,68.17 21.8,69.95 21.8,88.89 20.03,90.67 17.59,90.67 17.44,90.52 8.44,90.52 J1.28
D1: length 43.7
  TOP w0.15: 18.75,90.03 17.5,90.03 17.34,90.2 10.66,90.2 J1.27 ; 18.75,67.53 17.36,67.53 16.42,68.47 16.42,71.4 16.81,71.79 v1(16.81,72.61)
  BOTTOM w0.15: v1(16.81,72.61) 16.81,75.16 14.14,77.82 13.21,77.82 13.04,77.65 6.8,77.65 5.99,78.46 5.99,85.53 J1.27
D2: length 65.7
  TOP w0.15: U3.29 19.98,66.26 22.1,68.38 22.1,89.5 19.56,92.03 16.68,92.03 15.82,92.89 6.83,92.89 5.69,91.74 5.69,85.31 J1.26 8.42,85.42 13.09,85.42 16.29,88.62 17.44,88.62 17.59,88.76 U4.29
D3: length 39.7
  TOP w0.15: v1(17.54,74.07) 16.71,74.07 16.08,73.44 16.08,66.57 16.87,65.77 17.44,65.77 17.59,65.63 U3.30 ; v1(20.34,88.13) U4.30
  BOTTOM w0.15: J1.25 8.23,80.23 13.46,80.23 13.92,79.78 17.54,79.78 ; v1(17.54,74.07) 17.54,79.78 ; 17.54,79.78 17.54,85.33 v1(20.34,88.13)
D4: length 41.4
  TOP w0.15: U3.32 17.59,64.36 17.49,64.26 16.38,64.26 15.49,65.15 15.49,66.9 12.32,70.07 6.78,70.07 5.39,71.47 5.39,77.31 J1.24 8.91,80.83 8.91,82.35 11.69,85.12 14.45,85.12 16.04,86.71 17.44,86.71 17.59,86.86 U4.32
D5: length 41.3
  TOP w0.15: U4.33 20.16,86.22 21.43,84.95 21.43,76.33 21.07,75.97 v1(21.07,75.16) 12.97,75.16 12.92,75.11 8.27,75.11 J1.23 ; U3.33 v1(20.7,63.72)
  BOTTOM w0.15: v1(20.7,63.72) 21.07,64.1 v1(21.07,75.16)
D6: length 46.9
  TOP w0.15: U4.35 v1(20.34,84.95) ; U3.35 v1(20.34,62.45)
  BOTTOM w0.15: 13.39,71.27 16.54,71.27 18.58,73.31 18.58,83.19 v1(20.34,84.95) ; 13.39,71.27 13.39,70.96 12.5,70.07 11.78,70.07 10.77,69.06 10.77,68.42 11.7,67.49 13.01,67.49 13.15,67.63 17.16,67.63 19.95,64.84 19.95,62.84 v1(20.34,62.45) ; 13.39,71.27 13.39,71.6 12.38,72.61 8.23,72.61 J1.22
D7: length 38.8
  TOP w0.15: U3.36 16.07,61.82 v1(15.93,61.96) ; U4.36 17.59,84.32 17.49,84.42 14.73,84.42 13.09,82.77 11.89,82.77 10.11,81 10.11,80.49 7.32,77.69 6.88,77.69 5.99,76.8 5.99,72.31 J1.21
  BOTTOM w0.15: v1(15.93,61.96) 12.9,64.99 11.75,64.99 9.21,67.53 9.21,69.09 J1.21
D8: length 16.7
  TOP w0.15: J1.4 10.71,31.83 10.71,33.37 11.86,34.51 12.89,34.51 16.29,37.91 17.49,37.91 17.59,37.82 U1.36
D9: length 15.8
  TOP w0.15: U1.35 17.59,38.45 17.44,38.31 15.55,38.31 14.1,36.86 11.74,36.86 10.11,35.23 10.11,33.77 J1.5
D10: length 14.5
  TOP w0.15: U1.33 17.59,39.72 17.49,39.82 15.23,39.82 12.57,37.16 10.96,37.16 J1.6
D11: length 13.7
  TOP w0.15: U1.32 17.59,40.36 17.44,40.21 15.05,40.21 14.24,39.4 10.66,39.4 J1.7
D12: length 13.2
  TOP w0.15: U1.30 17.59,41.63 17.49,41.73 14.76,41.73 12.73,39.7 8.42,39.7 J1.8
D13: length 12.3
  TOP w0.15: J1.9 8.12,41.94 12.95,41.94 13.04,42.02 17.27,42.02 17.5,42.26 U1.29
D14: length 12.7
  TOP w0.15: J1.10 8.01,42.35 13.95,42.35 15.23,43.63 17.49,43.63 17.59,43.53 18.75,43.53
D15: length 12.5
  TOP w0.15: 18.75,44.17 15.14,44.17 14.64,44.67 8.23,44.67 J1.11
DATA: length 18.4
  TOP w0.15: U5.14 v1(39.55,109.16)
  BOTTOM w0.15: U7.1 30.23,99.72 30.23,101.67 37.72,109.16 v1(39.55,109.16)
DCLK: length 29.5
  TOP w0.15: U5.10 40.07,111.66 39.48,111.06 36.05,111.06 35.44,110.46 35.44,109.22 36.13,108.53 38.43,108.53 39.93,107.03 39.93,102.47 39.53,102.08 38.73,102.08 38.63,102.17 35.87,102.17 35.77,102.08 30.04,102.08 U7.2
DDIR: length 71.7
  TOP w0.15: 20.38,54.2 v1(20.38,52.59) 21.37,51.6 21.37,31.58 19.98,30.2 U1.48 ; 20.38,54.2 U3.48 ; 20.38,54.2 v1(20.38,61.03) ; U4.48 v1(20.34,76.7)
  BOTTOM w0.15: v1(20.38,52.59) 38.3,52.59 U2.20 ; v1(20.38,61.03) 21.8,62.45 21.8,76.06 21.17,76.7 v1(20.34,76.7)
DEN: length 58.6
  TOP w0.15: 35.83,50.12 U2.21 ; 35.83,50.12 35.53,50.42 v1(35.53,55.45) ; 35.83,50.12 35.83,36.53 29.5,30.2 28.25,30.2 ; 28.25,76.7 v1(30.84,76.7)
  BOTTOM w0.15: v1(30.84,76.7) 32.61,76.7 35.53,73.78 v1(35.53,55.45)
DHEN: length 16
  TOP w0.15: 28.25,54.2 28.97,54.2 30.15,53.02 v1(30.15,47.58)
  BOTTOM w0.15: U2.22 v1(30.15,47.58)
FPGA: length 33.5
  TOP w0.15: U5.30 v1(39.24,88.84)
  BOTTOM w0.15: U2.18 39.24,58.62 v1(39.24,88.84)
GAIN: length 106.1
  TOP w0.15: U13.6 87.33,24.21 87.84,24.72 87.84,28.49 82.85,33.48 81.2,33.48 78.66,36.02 v1(78.66,46.02) 79.7,47.05 82.49,47.05 85.4,44.13 U10.6 ; U5.28 v1(41.34,91.38)
  BOTTOM w0.15: v1(41.34,91.38) 48.39,91.38 57.91,81.86 57.91,80.12 68.74,69.3 68.74,55.94 v1(78.66,46.02)
HS: length 38.7
  TOP w0.15: U5.29 v1(40.28,90.11)
  BOTTOM w0.15: U2.19 40.28,57.11 v1(40.28,90.11)
LED1: length 33.8
  TOP w0.15: D1.C 87.32,60 87.32,61 87.04,61 87.04,60 86.77,60 86.77,61 86.49,61 86.49,60 86.21,60 86.21,61 85.93,61 85.93,60 85.66,60 85.66,61 85.38,61 85.38,60 85.1,60 85.1,61 84.83,61 84.83,60 84.55,60 84.55,61 84.27,61 84.27,60 84,60 84,61 83.72,61 83.72,60 83.44,60 83.44,61 83.16,61 83.16,60 82.89,60 82.89,61 82.61,61 82.61,60 R1.2
LED2: length 33.8
  TOP w0.15: R2.2 82.56,57.5 82.56,58.5 82.83,58.5 82.83,57.5 83.11,57.5 83.11,58.5 83.39,58.5 83.39,57.5 83.66,57.5 83.66,58.5 83.94,58.5 83.94,57.5 84.22,57.5 84.22,58.5 84.5,58.5 84.5,57.5 84.77,57.5 84.77,58.5 85.05,58.5 85.05,57.5 85.33,57.5 85.33,58.5 85.6,58.5 85.6,57.5 D2.C
LED3: length 33.8
  TOP w0.15: R3.2 82.5,55 82.5,56 82.78,56 82.78,55 83.06,55 83.06,56 83.33,56 83.33,55 83.61,55 83.61,56 83.89,56 83.89,55 D3.C
LED4: length 33.8
  TOP w0.15: R4.2 D4.C
MCLK: length 48.2
  TOP w0.15: U5.31 36.27,87.57 30.48,93.37 v1(21.43,93.37)
  BOTTOM w0.15: J1.52 14.56,68.76 18.88,73.08 18.88,78.55 21.43,81.11 v1(21.43,93.37)
MEMORY.RA0: length 202.8
  TOP w0.15: v1(100.77,98.22) v1(100.77,100.14) ; 103.34,94.27 103.69,93.91 103.69,88.64 103.58,88.53 103.58,85.89 103.06,85.37 U21.5 ; 103.34,94.27 103.06,93.98 U22.5 ; 103.34,94.27 v1(103.34,96.66) ; U17.5 79.06,80.44 78.45,81.05 78.45,81.19 v1(79.49,82.22) ; 71.69,104.81 71.99,104.52 71.99,97.75 71.56,97.31 71.56,84.73 68.86,82.03 68.86,75.56 72.92,71.5 74.14,71.5 74.44,71.8 78.27,71.8 79.06,71.01 v1(79.06,70.2) U16.5 ; 71.69,104.81 v1(71.69,105.6) ; 71.69,104.81 71.59,104.72 64.54,104.72 63.29,105.96 63.29,107.36 59.12,111.54 U5.79 ; U18.5 v1(79.06,94.4) ; U19.5 79.06,107.18 v1(78.84,107.4) ; U23.5 v1(103.06,103.91) ; U20.5 v1(103.06,64.94)
  BOTTOM w0.15: 101.07,96.66 100.77,96.96 v1(100.77,98.22) ; 101.07,96.66 v1(103.34,96.66) ; 101.07,96.66 99.84,95.43 95.47,95.43 93.41,93.36 80.09,93.36 v1(79.06,94.4) ; v1(79.49,82.22) 79.49,70.63 v1(79.06,70.2) 79.06,69.42 81.98,66.5 101.5,66.5 v1(103.06,64.94) ; v1(103.06,103.91) 103.06,102.43 v1(100.77,100.14) 99.9,99.27 97.44,99.27 95.15,101.56 95.15,103.26 93.25,105.16 78.97,105.16 78.54,105.6 ; 78.54,105.6 v1(71.69,105.6) ; 78.54,105.6 78.84,105.9 v1(78.84,107.4)
MEMORY.RA1: length 164.6
  TOP w0.15: 77.27,92.64 77.15,92.52 77.15,88.09 76.32,87.26 76.32,83.69 v1(77.05,82.96) 77.78,82.23 U17.4 ; 77.27,92.64 77.27,91.59 77.15,91.7 77.15,93.86 77.27,93.97 77.27,101.03 77.15,101.14 77.15,103.3 77.27,103.41 77.27,103.75 77.78,104.27 U19.4 77.78,108.05 79.03,109.3 v1(79.84,109.3) v1(92.98,109.3) ; 77.27,92.64 77.64,92.64 U18.4 ; U22.4 101.78,95.5 102.31,96.03 102.31,101.03 102.42,101.14 102.42,103.3 101.78,103.93 U23.4 101.78,108.16 100.64,109.3 v1(95.48,109.3) ; v1(98.51,68.61) 98.51,65.92 99.27,65.16 v1(100.24,65.16) 101.43,65.16 101.78,65.52 U20.4 ; v1(99.23,82.2) 101.15,82.2 101.78,81.56 U21.4 ; U16.4 v1(77.78,71.06) ; v1(60.39,115.19) U5.78
  BOTTOM w0.15: v1(60.39,115.19) 62.55,113.03 76.11,113.03 v1(79.84,109.3) ; v1(98.51,68.61) 98.51,81.48 v1(99.23,82.2) ; v1(95.48,109.3) v1(92.98,109.3) ; v1(77.05,82.96) 77.05,71.8 v1(77.78,71.06) 77.78,70.21 82.1,65.9 99.5,65.9 v1(100.24,65.16)
MEMORY.RA2: length 169.7
  TOP w0.15: v1(96.72,104.44) 100.44,104.44 100.52,104.52 U23.3 ; v1(76.29,81.25) 76.29,80 U17.3 ; U22.3 100.52,91.52 100.3,91.3 98.51,91.3 ; U21.3 v1(100.52,78.81) ; v1(96.07,93.06) 96.72,93.72 v1(96.72,101.33) ; v1(99.14,100) 97.45,98.31 97.45,91.69 97.85,91.3 98.51,91.3 ; U5.77 v1(61.66,111.24) ; v1(61.66,107.89) 60.44,106.67 60.44,97.19 64.35,93.28 67.11,93.28 67.33,93.06 v1(68.14,93.06) ; U16.3 v1(76.52,69.73) ; U18.3 v1(76.52,94.4) ; v1(98.51,85.46) 98.51,88.56 98.61,88.66 98.61,90.78 98.51,90.88 98.51,91.3 ; U20.3 v1(100.52,68.4) ; U19.3 v1(76.52,109.06)
  BOTTOM w0.15: v1(96.72,104.44) v1(96.72,101.33) 96.72,100.46 97.61,99.57 98.71,99.57 v1(99.14,100) ; v1(76.52,69.73) 76.29,69.95 v1(76.29,81.25) 75.66,81.25 68.14,88.77 v1(68.14,93.06) 76.52,93.06 ; v1(100.52,68.4) 100.52,68.4 v1(100.52,78.81) 100.52,83.46 v1(98.51,85.46) ; 76.52,93.06 v1(76.52,94.4) ; 76.52,93.06 v1(96.07,93.06) ; v1(76.52,109.06) 76.52,107.55 76.12,107.16 62.39,107.16 v1(61.66,107.89) v1(61.66,111.24)
MEMORY.RA3: length 172.9
  TOP w0.15: v1(75.03,109.26) 75.03,107.27 75.25,107.05 U19.2 ; U21.2 v1(99.25,78.21) ; U16.2 v1(75.25,68.4) ; U20.2 v1(99.25,69.77) ; v1(69.42,109.26) 69.42,110.08 68.53,110.97 67.23,110.97 67.13,111.06 63.52,111.06 62.93,111.66 U5.76 ; U17.2 v1(75.25,78.16) ; U22.2 99.25,93.88 v1(98.73,94.4) 97.96,95.16 97.96,97.49 99.88,99.4 99.88,103.31 99.48,103.7 96.39,103.7 95.99,104.1 95.99,105.38 97.58,106.97 98.44,106.97 99.25,106.17 U23.2 ; v1(72.29,109.26) 72.42,109.13 v1(72.42,94.4) v1(72.42,89.74) 72.42,75.61 74.33,73.7 v1(75.17,73.7) ; U18.2 v1(75.25,94.4)
  BOTTOM w0.15: v1(75.25,78.16) 75.25,73.78 v1(75.17,73.7) 75.17,68.47 v1(75.25,68.4) ; v1(75.03,109.26) v1(72.29,109.26) v1(69.42,109.26) ; v1(75.25,94.4) v1(72.42,94.4) ; 81.83,89.74 94.92,89.74 98.73,93.55 v1(98.73,94.4) ; 81.83,89.74 v1(72.42,89.74) ; 81.83,89.74 81.83,86.74 82.59,85.97 89.16,85.97 96.15,78.99 96.15,69.91 98.18,67.87 98.85,67.87 99.25,68.27 v1(99.25,69.77) v1(99.25,78.21)
MEMORY.RA4: length 138.8
  TOP w0.15: 73.45,100.73 73.75,100.73 73.97,100.95 U18.32 ; 73.45,100.73 73.45,89.08 ; 73.45,100.73 73.02,101.17 v1(73.02,111.19) 73.02,114.99 ; U5.71 67.34,107.89 68.29,108.84 v1(68.29,110.16) ; 97.16,89.36 97.16,76.44 97.38,76.22 U20.32 ; 97.16,89.36 97.16,99.48 v1(97.98,100.3) 97.37,100.9 97.37,100.95 97.97,101.56 U22.32 ; 97.16,89.36 97.61,89.36 U21.32 ; 73.02,114.99 v1(73.02,115.13) ; 73.02,114.99 73.74,114.99 U19.32 ; 73.45,89.08 73.45,78.27 73.97,77.75 U16.32 ; 73.45,89.08 73.83,89.08 U17.32 ; U23.32 97.97,114.56 97.37,113.95 95.75,113.95 v1(94.58,115.13)
  BOTTOM w0.15: v1(73.02,115.13) v1(94.58,115.13) ; v1(97.98,100.3) 97.98,104.24 96.45,105.76 82.07,105.76 79.71,108.13 78.56,108.13 75.5,111.19 v1(73.02,111.19) 71.99,110.16 v1(68.29,110.16)
MEMORY.RA5: length 147.9
  TOP w0.15: U23.31 99.25,114.35 v1(98.5,113.6) 98.5,114.03 98.61,114.14 98.61,116.28 96.59,118.3 77.75,118.3 76.73,117.29 76.73,116.41 ; U16.31 75.25,76.89 77.15,78.79 77.15,81.67 75.25,83.57 v1(75.25,87.6) U17.31 ; 76.73,116.41 77.15,116.41 77.15,112.45 75.77,111.06 v1(75.77,107.89) 75.77,106.97 75.88,106.86 75.88,104.69 75.25,104.05 U18.31 v1(75.25,100.37) ; 76.73,116.41 76.05,116.41 75.25,115.61 U19.31 ; 95.69,103.41 95.69,105.67 97.72,107.7 v1(98.5,107.7) ; 95.69,103.41 98.44,103.41 99.25,102.61 U22.31 ; 95.69,103.41 95.34,103.06 95.34,88.35 v1(96.12,87.57) 96.12,76.43 97.52,75.03 98.44,75.03 99.25,75.83 U20.31 ; U21.31 v1(99.25,87.57) ; v1(70.82,87.6) 71.25,88.03 v1(71.25,100.37) ; U5.70 68.06,106.62 v1(69.33,107.89)
  BOTTOM w0.15: v1(98.5,107.7) v1(98.5,113.6) ; v1(70.82,87.6) v1(75.25,87.6) ; v1(69.33,107.89) v1(75.77,107.89) ; v1(75.25,100.37) v1(71.25,100.37) ; v1(99.25,87.57) v1(96.12,87.57)
MEMORY.RA6: length 172.6
  TOP w0.15: 74.51,99.56 74.51,101.06 74.61,101.16 74.61,107.96 74.29,108.28 74.29,113.81 74.51,114.03 ; 74.51,99.56 75.5,99.56 76.52,100.58 U18.30 ; 74.51,99.56 74.51,93.94 74.61,93.84 74.61,91.72 74.51,91.62 74.51,90.41 ; 74.51,116.41 74.51,116.38 74.61,116.28 74.61,114.13 74.51,114.03 ; 74.51,116.41 76.71,118.6 98.4,118.6 100.52,116.48 U23.30 100.52,113.52 v1(100.29,113.29) ; 74.51,116.41 73.25,116.41 70.45,113.61 70.45,107.89 67.91,105.35 U5.69 ; 74.51,90.41 74.61,90.31 74.61,88.16 74.51,88.06 74.51,80.94 74.61,80.84 74.61,78.72 74.51,78.62 74.51,77.38 74.61,77.28 74.61,75.19 74.85,74.95 75.91,74.95 76.52,75.56 U16.30 ; 74.51,90.41 75.72,90.41 76.52,89.61 U17.30 ; 74.51,114.03 75.72,114.03 76.52,114.83 U19.30 ; U22.30 100.52,103.48 101.15,104.12 101.15,107.67 v1(100.29,108.52) 98.01,108.52 95.34,105.86 95.34,104.46 95.04,104.15 95.04,77.02 97.32,74.73 99.69,74.73 100.52,75.56 U20.30 100.52,76.61 99.72,77.41 98.98,77.41 97.45,78.93 97.45,83.29 100.52,86.35 U21.30
  BOTTOM w0.15: v1(100.29,108.52) v1(100.29,113.29)
MEMORY.RA7: length 181
  TOP w0.15: 78,87.73 77.78,87.95 U17.29 ; 78,87.73 v1(78,85.36) 80.08,85.36 82.12,87.39 82.12,88.03 82.23,88.14 82.23,90.19 82.75,90.7 84.91,90.7 86.04,91.84 86.04,93.87 87.17,95 v1(87.98,95) ; 78,87.73 78.42,88.15 78.42,93.86 78.31,93.97 78.31,94.31 77.78,94.83 U18.29 77.78,103.48 78,103.7 78.56,103.7 79.69,104.84 79.69,106.98 79.97,107.27 80.45,107.27 81.06,106.66 v1(81.06,103.84) ; 101.25,76.33 101.67,76.33 U20.29 ; 101.25,76.33 101.15,76.23 101.15,75.1 100.49,74.44 89.37,74.44 88.58,75.23 88.58,77.21 87.78,78 83,78 82.23,78.78 82.23,80.8 82.02,81.01 81.2,81.01 80.96,80.77 80.96,78.78 80.04,77.86 v1(77.78,77.86) U16.29 ; 101.25,76.33 101.25,79.12 101.15,79.22 101.15,81.31 101,81.47 98.89,81.47 98.49,81.86 98.49,82.74 101.78,86.03 U21.29 ; v1(99.52,97.41) 101.02,97.41 101.78,98.17 U22.29 ; U23.29 v1(101.78,116.84) ; v1(69.49,103.84) 68.46,102.81 U5.67 ; v1(77.78,117.2) U19.29 77.78,111.5 77.25,110.97 77.25,106.94 77.15,106.84 77.15,104.49 v1(76.5,103.84)
  BOTTOM w0.15: v1(101.78,116.84) 87.03,116.84 86.3,117.57 78.97,117.57 78.6,117.2 v1(77.78,117.2) ; v1(81.06,103.84) v1(76.5,103.84) v1(69.49,103.84) ; v1(77.78,77.86) 78,78.08 v1(78,85.36) ; v1(87.98,95) 88.72,95.73 99.01,95.73 99.52,96.24 v1(99.52,97.41)
MEMORY.RA8: length 148.5
  TOP w0.15: 102.75,110.63 103.69,109.69 103.69,104.72 103.79,104.62 103.79,102.35 103.66,102.22 U22.28 103.06,100.95 102.61,100.5 102.61,94.9 102.42,94.72 102.42,91.7 102.53,91.59 102.53,91.59 ; 102.75,110.63 103.06,110.93 U23.28 ; 102.75,110.63 v1(96.64,110.63) ; v1(87.98,96.41) 83.7,96.41 83.4,96.11 ; v1(91.31,110.63) 89.48,110.63 88.47,111.64 88.47,114.03 88.58,114.14 88.58,116.19 87.19,117.57 79.94,117.57 79.06,116.68 U19.28 ; 102.53,91.59 102.19,91.25 101.63,91.25 101.15,91.73 101.15,94.01 v1(98.7,96.46) ; 102.53,91.59 102.83,91.3 102.83,90.91 ; U21.28 103.06,90.91 102.83,90.91 ; 102.83,90.91 102.53,90.91 102.42,90.79 102.42,78.68 103.06,78.05 U20.28 ; v1(79.06,87.33) U17.28 79.06,90.48 79.88,91.31 83.01,91.31 83.5,91.8 83.5,93.84 83.4,93.93 83.4,96.11 ; U5.66 v1(71.25,101.54) ; 83.4,96.11 80.23,96.11 78.45,97.89 78.45,100 v1(79.06,100.6) U18.28 ; U16.28 79.06,74.6 v1(78.75,74.3)
  BOTTOM w0.15: v1(87.98,96.41) 98.64,96.41 v1(98.7,96.46) ; v1(79.06,100.6) 78.12,101.54 v1(71.25,101.54) ; v1(91.31,110.63) v1(96.64,110.63) ; v1(79.06,87.33) 78.75,87.03 v1(78.75,74.3)
MEMORY.RA9: length 163.9
  TOP w0.15: U18.22 86.53,102.36 86.16,102.36 ; 86.16,102.36 86.04,102.25 86.04,101.22 85.27,100.45 v1(83.66,100.45) ; 86.16,102.36 86.16,104.59 86.04,104.7 86.04,106.86 86.16,106.97 86.16,107.44 86.41,107.7 v1(87.25,107.7) ; v1(111.16,100.75) 111.16,101.74 U22.22 ; 85.5,83.77 85.5,85.24 86.67,86.42 U17.22 ; 85.5,83.77 78.45,83.77 77.18,85.04 v1(77.18,86.53) ; 85.5,83.77 86.08,83.77 86.14,83.7 v1(86.14,82.89) ; v1(86.67,113.01) U19.22 ; U21.22 110.67,86.64 111.7,85.62 v1(111.7,83.7) 110.04,82.04 110.04,79.2 110.16,79.09 110.16,77.41 110.04,77.3 110.04,75.14 110.16,75.03 110.16,76.08 ; v1(69.7,89.82) v1(69.7,100) 69.43,100.27 U5.65 ; U20.22 110.53,76.08 110.16,76.08 ; 110.16,76.08 110.16,74.73 107.91,72.49 v1(89.18,72.49) ; U23.22 110.67,114.56 109.88,113.76 109.88,112.78 v1(110.45,112.2) ; U16.22 v1(86.67,74.6)
  BOTTOM w0.15: v1(83.66,100.45) 82.7,99.49 71.02,99.49 70.51,100 v1(69.7,100) ; v1(87.25,107.7) 87.25,112.43 v1(86.67,113.01) ; v1(86.14,82.89) 86.14,75.14 v1(86.67,74.6) 88.78,72.49 v1(89.18,72.49) ; v1(69.7,89.82) 69.7,87.67 70.84,86.53 v1(77.18,86.53) ; v1(110.45,112.2) 111.16,111.5 v1(111.16,100.75) 111.16,98.1 111.33,97.93 111.33,84.88 111.7,84.51 v1(111.7,83.7)
MEMORY.RA10: length 147.9
  TOP w0.15: 87.94,98.38 v1(79.49,98.38) ; 87.94,98.38 U18.21 v1(87.94,103.84) ; 87.94,98.38 89.02,97.31 89.02,94.36 88.58,93.92 88.58,91.68 87.94,91.05 U17.21 v1(87.94,84.06) ; v1(89.94,103.84) v1(89.94,108.13) 92.91,108.13 93.71,108.94 93.71,109.63 93.31,110.03 92.11,110.03 91.98,109.89 89.72,109.89 87.94,111.67 U19.21 ; U23.21 111.94,112.22 v1(112.03,112.14) ; U21.21 111.94,86.83 v1(112.17,86.61) 113.73,85.04 113.73,81.47 113.85,81.36 113.85,79.28 113.48,78.91 113.22,78.91 111.94,77.64 U20.21 ; U5.64 67.67,99 v1(68.29,98.38) ; v1(112.03,99.34) 111.94,99.43 U22.21 ; v1(87.84,74.6) 87.94,74.7 U16.21
  BOTTOM w0.15: v1(87.94,84.06) 87.94,74.7 v1(87.84,74.6) ; v1(112.17,86.61) 112.03,86.75 v1(112.03,99.34) v1(112.03,112.14) 111.23,112.93 106.13,112.93 105.9,112.7 105.53,112.7 99.8,106.97 93.02,106.97 91.86,108.13 v1(89.94,108.13) ; v1(79.49,98.38) v1(68.29,98.38) ; v1(89.94,103.84) v1(87.94,103.84)
MEMORY.RA11: length 143.5
  TOP w0.15: 88.91,100.73 89,100.73 89.22,100.95 U18.20 ; 88.91,100.73 88.58,101.07 88.58,103.3 88.69,103.41 88.69,104.59 88.58,104.7 88.58,106.86 88.69,106.97 v1(88.69,108.52) ; 88.91,100.73 v1(88.91,99.34) 89.85,98.4 89.85,91.68 89.22,91.05 U17.20 89.22,87.95 88.69,87.44 88.69,80.97 88.58,80.86 88.58,78.68 89.22,78.05 U16.20 ; v1(89.22,111.96) U19.20 v1(89.22,117.57) ; U21.20 v1(113.22,88.08) ; v1(113.73,100.6) 113.22,101.12 U22.20 ; v1(113.73,113.6) 113.22,114.12 U23.20 v1(113.22,117.57) ; U20.20 v1(113.22,77.84) ; U5.63 v1(63.54,97.73)
  BOTTOM w0.15: v1(63.54,97.73) 64.94,96.33 86.11,96.33 88.91,99.13 v1(88.91,99.34) ; v1(89.22,111.96) 88.69,111.44 v1(88.69,108.52) ; v1(113.73,113.6) v1(113.73,100.6) 113.73,88.6 v1(113.22,88.08) v1(113.22,77.84) ; v1(89.22,117.57) v1(113.22,117.57)
